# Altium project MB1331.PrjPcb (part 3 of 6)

## Sheet Audio_Codec.SchDoc: Audio Codec
size A4; Date: Not used; ApprovedBy: Not used; CheckedBy: Not used; Author: Not used; CompanyName: STMicroelectronics; DrawnBy: Not used; Engineer: Not used; Organization: Not used; Address1: Not used; Address2: Not used; Address3: Not used; Address4: Not used; DocumentNumber: Not used; Revision: Not used; SheetNumber: 10; SheetTotal: 23
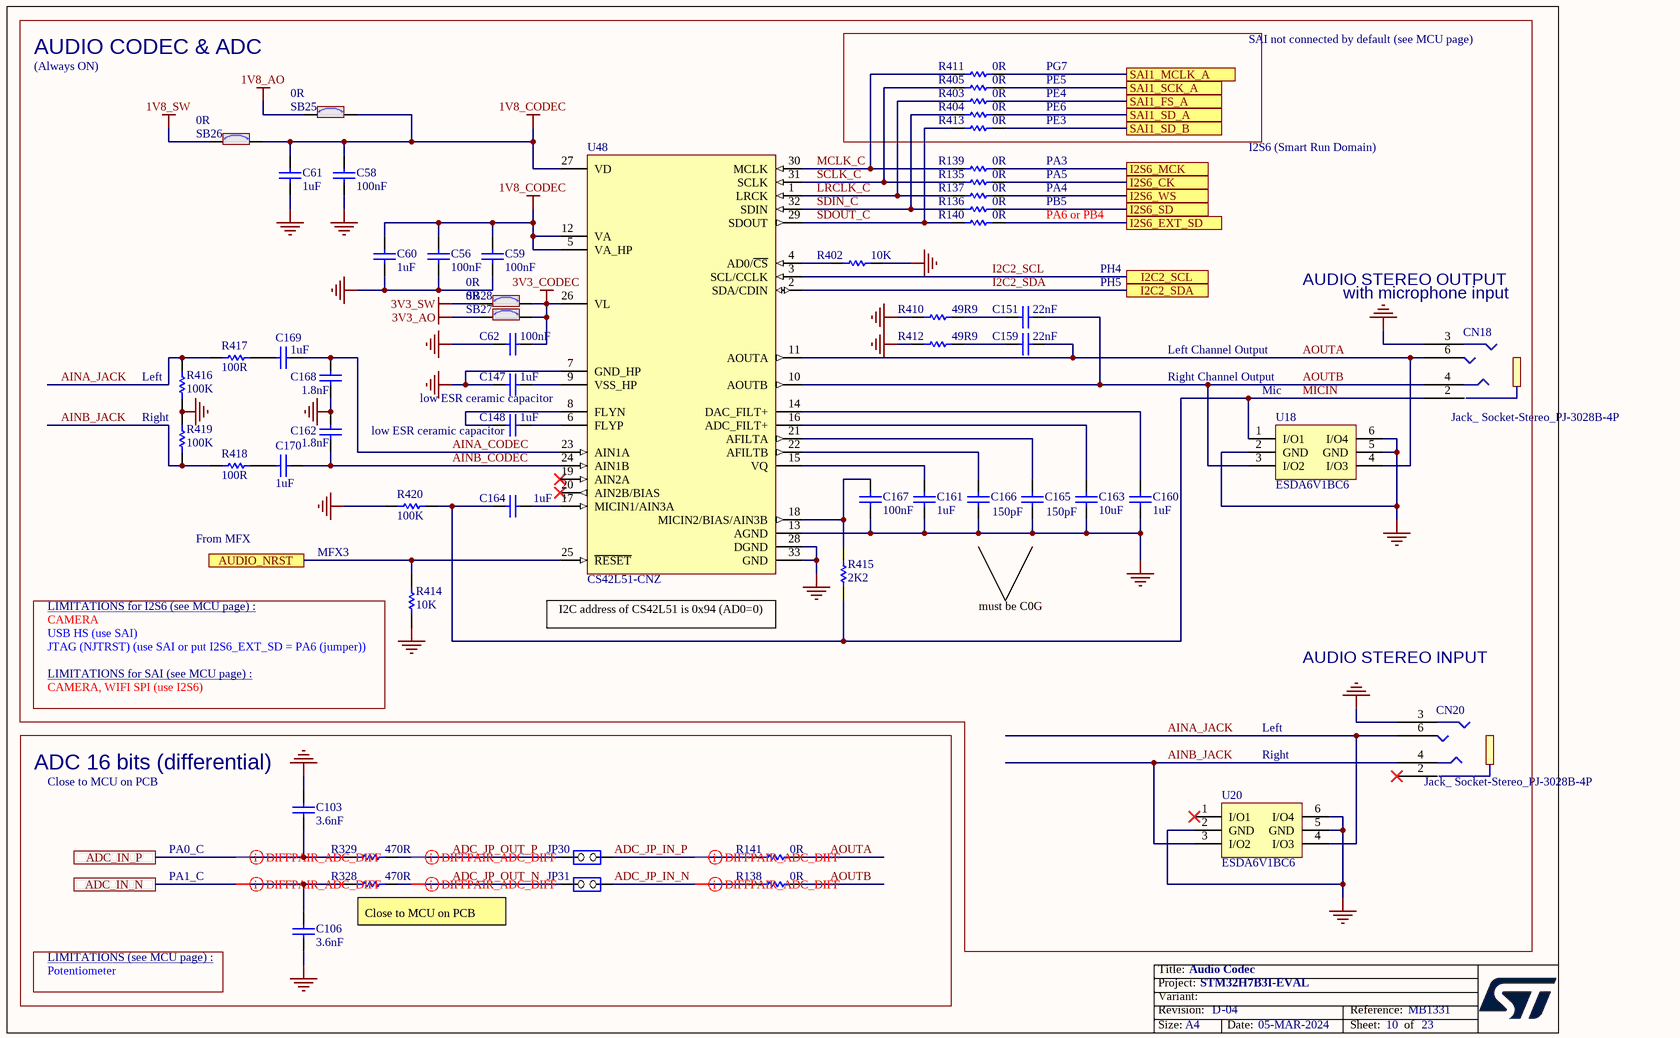
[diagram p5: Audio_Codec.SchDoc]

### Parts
C56  value 100nF  [C0402]  (hidden comment: Capacitor)
C58  value 100nF  [C0402]  (hidden comment: Capacitor)
C59  value 100nF  [C0402]  (hidden comment: Capacitor)
C60  value 1uF  [C0603]  (hidden comment: Capacitor)
C61  value 1uF  [C0603]  (hidden comment: Capacitor)
C62  value 100nF  [C0402]  (hidden comment: Capacitor)
C103  value 3.6nF  [C0603]  (hidden comment: Capacitor)
C106  value 3.6nF  [C0603]  (hidden comment: Capacitor)
C147  value 1uF  [C0603]  (hidden comment: Capacitor)
C148  value 1uF  [C0603]  (hidden comment: Capacitor)
C151  value 22nF  [C0603]  (hidden comment: Capacitor)
C159  value 22nF  [C0603]  (hidden comment: Capacitor)
C160  value 1uF  [C0603]  (hidden comment: Capacitor)
C161  value 1uF  [C0603]  (hidden comment: Capacitor)
C162  value 1.8nF  [C0402]  (hidden comment: Capacitor)
C163  value 10uF  [C0603]  (hidden comment: Capacitor)
C164  value 1uF  [C0603]  (hidden comment: Capacitor)
C165  value 150pF  [C0603]  (hidden comment: Capacitor)
C166  value 150pF  [C0603]  (hidden comment: Capacitor)
C167  value 100nF  [C0402]  (hidden comment: Capacitor)
C168  value 1.8nF  [C0402]  (hidden comment: Capacitor)
C169  value 1uF  [C0402]  (hidden comment: Capacitor)
C170  value 1uF  [C0402]  (hidden comment: Capacitor)
CN18  value Jack_ Socket-Stereo_PJ-3028B-4P  [CON_PHONE-JACK-3P5_HY_PJ3028B]  (hidden comment: Jack_PJ3028B-3_4P)
CN20  value Jack_ Socket-Stereo_PJ-3028B-4P  [CON_PHONE-JACK-3P5_HY_PJ3028B]  (hidden comment: Jack_PJ3028B-3_4P)
JP30  Jumper_Header 2x1  [CON_SAMTEC_TSW-102-07-G-S]  (value not drawn)
JP31  Jumper_Header 2x1  [CON_SAMTEC_TSW-102-07-G-S]  (value not drawn)
R135  value 0R  [R0402]  (hidden comment: Resistor)
R136  value 0R  [R0402]  (hidden comment: Resistor)
R137  value 0R  [R0402]  (hidden comment: Resistor)
R138  value 0R  [R0603]  (hidden comment: Resistor)
R139  value 0R  [R0402]  (hidden comment: Resistor)
R140  value 0R  [R0402]  (hidden comment: Resistor)
R141  value 0R  [R0603]  (hidden comment: Resistor)
R328  value 470R  [R0402]  (hidden comment: Resistor)
R329  value 470R  [R0402]  (hidden comment: Resistor)
R402  value 10K  [R0402]  (hidden comment: Resistor)
R403  value 0R  [R0402]  (hidden comment: Resistor)
R404  value 0R  [R0402]  (hidden comment: Resistor)
R405  value 0R  [R0402]  (hidden comment: Resistor)
R410  value 49R9  [R0603]  (hidden comment: Resistor)
R411  value 0R  [R0402]  (hidden comment: Resistor)
R412  value 49R9  [R0603]  (hidden comment: Resistor)
R413  value 0R  [R0402]  (hidden comment: Resistor)
R414  value 10K  [R0402]  (hidden comment: Resistor)
R415  value 2K2  [R0603]  (hidden comment: Resistor)
R416  value 100K  [R0402]  (hidden comment: Resistor)
R417  value 100R  [R0402]  (hidden comment: Resistor)
R418  value 100R  [R0402]  (hidden comment: Resistor)
R419  value 100K  [R0402]  (hidden comment: Resistor)
R420  value 100K  [R0603]  (hidden comment: Resistor)
SB25  value 0R  [SOLDER-BRIDGE_R0603-0R]  (hidden comment: SB_ON)
SB26  value 0R  [SOLDER-BRIDGE_R0603-0R]  (hidden comment: SB_ON)
SB27  value 0R  [SOLDER-BRIDGE_R0603-0R]  (hidden comment: SB_ON)
SB28  value 0R  [SOLDER-BRIDGE_R0603-0R]  (hidden comment: SB_ON)
U18  ESDA6V1BC6  [ESD_SOT23-6L]
U20  ESDA6V1BC6  [ESD_SOT23-6L]
U48  CS42L51-CNZ  [ICC_QFN32-EPAD_5X5_P050]

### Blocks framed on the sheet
AUDIO CODEC & ADC: C56 C58-C62 C147 C148 C151 C159-C170 CN18 CN20 R135-R137 R139 R140 R402-R405 R410-R420 SB25-SB28 U18 U20 U48
ADC 16 bits (differential): C103 C106 JP30 JP31 R138 R141 R328 R329

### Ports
ADC_IN_N, ADC_IN_P, AUDIO_NRST, I2C2_SCL, I2C2_SDA, I2S6_CK, I2S6_EXT_SD, I2S6_MCK, I2S6_SD, I2S6_WS, SAI1_FS_A, SAI1_MCLK_A, SAI1_SCK_A, SAI1_SD_A, SAI1_SD_B

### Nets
1V8_AO: SB25.1
1V8_CODEC: C56.2 C58.2 C59.2 C60.1 C61.1 SB25.2 SB26.2 U48.5(VA_HP) U48.12(VA) U48.27(VD)
1V8_SW: SB26.1
3V3_AO: SB27.1
3V3_CODEC: C62.1 SB27.2 SB28.2 U48.26(VL)
3V3_SW: SB28.1
GND: C56.1 C58.1 C59.1 C60.2 C61.2 C62.2 C103.2 C106.1 C147.1 C160.1 C161.1 C162.2 C163.1 C165.2 C166.2 C167.2 C168.1 CN18.3 CN20.3 R402.2 R410.1 R412.1 R414.1 R416.1 R419.2 R420.1 U18.2(GND) U18.5(GND) U18.6(I/O4) U20.2(GND) U20.5(GND) U20.6(I/O4) U48.7(GND_HP) U48.13(AGND) U48.28(DGND) U48.33(GND)
ADC_IN_N: C106.2 R328.1 ; port ADC_IN_N
ADC_IN_P: C103.1 R329.1 ; port ADC_IN_P
ADC_JP_IN_N: JP31.1(COMMON) R138.1
ADC_JP_IN_P: JP30.1(COMMON) R141.1
ADC_JP_OUT_N: JP31.2(NO) R328.2
ADC_JP_OUT_P: JP30.2(NO) R329.2
AINA_CODEC: C168.2 C169.2 U48.23(AIN1A)
AINA_JACK: CN20.6 R416.2 R417.1 U20.4(I/O3)
AINB_CODEC: C162.1 C170.2 U48.24(AIN1B)
AINB_JACK: CN20.4 R418.1 R419.1 U20.3(I/O2)
AOUTA: C159.2 CN18.6 R141.2 U18.4(I/O3) U48.11(AOUTA)
AOUTB: C151.2 CN18.4 R138.2 U18.3(I/O2) U48.10(AOUTB)
AUDIO_NRST: R414.2 U48.25(~{RESET}) ; port AUDIO_NRST
I2C2_SCL: U48.3(SCL/CCLK) ; port I2C2_SCL
I2C2_SDA: U48.2(SDA/CDIN) ; port I2C2_SDA
I2S6_CK: R135.2 ; port I2S6_CK
I2S6_EXT_SD: R140.2 ; port I2S6_EXT_SD
I2S6_MCK: R139.2 ; port I2S6_MCK
I2S6_SD: R136.2 ; port I2S6_SD
I2S6_WS: R137.2 ; port I2S6_WS
LRCLK_C: R137.1 R403.1 U48.1(LRCK)
MCLK_C: R139.1 R411.1 U48.30(MCLK)
MICIN: C164.1 CN18.2 R415.1 R420.2 U18.1(I/O1)
SAI1_FS_A: R403.2 ; port SAI1_FS_A
SAI1_MCLK_A: R411.2 ; port SAI1_MCLK_A
SAI1_SCK_A: R405.2 ; port SAI1_SCK_A
SAI1_SD_A: R404.2 ; port SAI1_SD_A
SAI1_SD_B: R413.2 ; port SAI1_SD_B
SCLK_C: R135.1 R405.1 U48.31(SCLK)
SDIN_C: R136.1 R404.1 U48.32(SDIN)
SDOUT_C: R140.1 R413.1 U48.29(SDOUT)
NetC147_2: C147.2 U48.9(VSS_HP)
NetC148_1: C148.1 U48.8(FLYN)
NetC148_2: C148.2 U48.6(FLYP)
NetC151_1: C151.1 R410.2
NetC159_1: C159.1 R412.2
NetC160_2: C160.2 U48.14(DAC_FILT+)
NetC161_2: C161.2 U48.15(VQ)
NetC163_2: C163.2 U48.16(ADC_FILT+)
NetC164_2: C164.2 U48.17(MICIN1/AIN3A)
NetC165_1: C165.1 U48.21(AFILTA)
NetC166_1: C166.1 U48.22(AFILTB)
NetC167_1: C167.1 R415.2 U48.18(MICIN2/BIAS/AIN3B)
NetC169_1: C169.1 R417.2
NetC170_1: C170.1 R418.2
NetR402_1: R402.1 U48.4(AD0/~{CS})

Not connected (* = marked no-connect by the designer): CN20 2*; U20 1(I/O1)*; U48 19(AIN2A)* 20(AIN2B/BIAS)*

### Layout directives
differential pair: ADC_IN_N, ADC_IN_P, ADC_JP_IN_N, ADC_JP_IN_P, ADC_JP_OUT_N, ADC_JP_OUT_P

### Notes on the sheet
- SAI not connected by default (see MCU page)
- (Always ON)
- PE6
- PE4
- PE5
- PG7
- PA5
- PA3
- PE3
- I2S6 (Smart Run Domain)
- PA4
- PA6 or PB4
- PB5
- PH4
- PH5
- AUDIO STEREO OUTPUT
- (near CN18) with microphone input
- (near R416) Left
- Left Channel Output
- Right Channel Output
- Right
- (near C148) low ESR ceramic capacitor
- low ESR ceramic capacitor
- (near U18) Mic
- From MFX
- MFX3
- LIMITATIONS for I2S6 (see MCU page) :
- CAMERA
- USB HS (use SAI)
- (near R414) JTAG (NJTRST) (use SAI or put I2S6_EXT_SD = PA6 (jumper))
- (near U48) I2C address of CS42L51 is 0x94 (AD0=0)
- must be C0G
- LIMITATIONS for SAI (see MCU page) :
- CAMERA, WIFI SPI (use I2S6)
- AUDIO STEREO INPUT
- Close to MCU on PCB
- Left
- PA0_C
- PA1_C
- (near R328) Close to MCU on PCB
- LIMITATIONS (see MCU page) :
- Potentiometer

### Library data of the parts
C56 C58 C59 C62 C167 = MCD-00006: Capacitor, MLCC, 100nF, 16V, X7R, 10%, 0402, T=0.5mm; Manufacturer_Part_Number: CC0402KRX7R7BB104; Manufacturer: YAGEO; Alternate_Manufacturer_Part_Number: GCM155R71C104KA55D; Alternate_Manufacturer: MURATA; Part_Preference: Recommended; Partial_Alternate_Internal_Part_Number: MCD-03299; Provided_By: SUBCO; ECCN_US: EAR99; ECCN_EU: NEC; Component_Country_Of_Origin: China; ID: 2474; Order_Code_RS: 9402047; ShowFields: YES
C60 C61 C147 C148 C160 C161 C164 = MCD-00010: Capacitor, MLCC, 1uF, 16V, X5R, 10%, 0603, T=0,8mm; Manufacturer_Part_Number: CC0603KRX5R7BB105; Manufacturer: YAGEO; Part_Preference: Recommended; Provided_By: SUBCO; ECCN_US: EAR99; ECCN_EU: NEC; Component_Country_Of_Origin: China; ID: 2470; Order_Code_RS: 2370680; ShowFields: YES
C103 C106 = MCD-00716: Capacitor, MLCC, 3.6nF, 50V, C0G, 5%, 0603, T=0,8mm; Manufacturer_Part_Number: C0603C362J5GACTU; Manufacturer: KEMET; Alternate_Manufacturer_Part_Number: GRM1885C1H362JA01D; Alternate_Manufacturer: MURATA; Part_Preference: Recommended; Provided_By: SUBCO; ECCN_US: EAR99; ECCN_EU: NEC; Component_Country_Of_Origin: Mexico; ID: 3031; ShowFields: YES
C151 C159 = MCD-00555: Capacitor, MLCC, 22nF, 10%, 25V, X7R, 0603, T=0,8mm; Manufacturer_Part_Number: CC0603KRX7R8BB223; Manufacturer: YAGEO; Part_Preference: Recommended; Provided_By: SUBCO; ECCN_US: EAR99; ECCN_EU: NEC; Component_Country_Of_Origin: China; ID: 3190; ShowFields: YES
C162 C168 = MCD-00694: Capacitor, MLCC, 1.8nF, 50V, X7R, 10%, 0402, T=0.5mm; Manufacturer_Part_Number: CC0402KRX7R9BB182; Manufacturer: YAGEO; Part_Preference: Recommended; Provided_By: SUBCO; Component_Country_Of_Origin: China; ID: 3045; ShowFields: YES
C163 = MCD-00099: Capacitor, MLCC, 10uF, 10V, X5R, 10%, 0603, T=0,8mm; Manufacturer_Part_Number: GRM188R61A106KE69D; Manufacturer: MURATA; Part_Preference: Recommended; Partial_Alternate_Internal_Part_Number: MCD-03152; Provided_By: SUBCO; ECCN_US: EAR99; ECCN_EU: NEC; Component_Country_Of_Origin: Japan°°; ID: 2770; Order_Code_RS: 2494233; ShowFields: YES
C165 C166 = MCD-00304: Capacitor, MLCC, 150pF, 50V, COG, 5%, 0603, T=0,8mm; Manufacturer_Part_Number: CC0603JRNPO9BN151; Manufacturer: YAGEO; BMS_Part_Number: 9142051; Part_Preference: Recommended; Provided_By: SUBCO; ECCN_US: EAR99; ECCN_EU: NEC; Component_Country_Of_Origin: China; ID: 2568; ShowFields: YES
C169 C170 = MCD-00095: Capacitor, MLCC, 1uF, 6V3, X5R, 10%, 0402, T=0,5mm; Manufacturer_Part_Number: GRM155R61E105KA12; Manufacturer: MURATA; Alternate_Manufacturer_Part_Number: GRM155R60J105KE19; Part_Preference: Recommended; Provided_By: SUBCO; ECCN_US: EAR99; ECCN_EU: NEC; Component_Country_Of_Origin: Japan°°; ID: 2772; Order_Code_RS: 2218855; ShowFields: YES
CN18 CN20 = MCD-00263: Connector Jack Socket Stereo 3.5mm, 4 pins, RA, SMT, Black; Manufacturer_Part_Number: PJ-3028B-4P; Manufacturer: QIAOD; Part_Preference: Recommended; Provided_By: SUBCO; Component_Country_Of_Origin: Unknown; ID: 2608; ShowFields: YES
JP30 JP31 = MCD-00045: Header, 2x1, 2,54mm, VR, TH, Height 5.84mm/2.54mm; Part_Type: Connector; Manufacturer_Part_Number: TSW-102-07-G-S; Manufacturer: SAMTEC; Alternate_Manufacturer_Part_Number: 313102S111116;313102S111116; Alternate_Manufacturer: JIUBABA; LIANYI; Full_Alternate_Internal_Part_Number: MCD-02390; Part_Preference: Recommended; Partial_Alternate_Internal_Part_Number: MCD-02957, MCD-03720; Provided_By: SUBCO; Component_Country_Of_Origin: China, Costa Rica, Malaysia, USA, Vietnam; ID: 2545; Order_Code_RS: 2505044; ShowFields: YES
R135-R137 R139 R140 R403-R405 R411 R413 = MCD-00052: Resistor,0R,0402,5%,1/16W; Manufacturer_Part_Number: RC0402JR-070RL; Manufacturer: YAGEO; Part_Preference: Recommended; Provided_By: SUBCO; ECCN_US: EAR99; ECCN_EU: NEC; Component_Country_Of_Origin: China; ID: 2540; Order_Code_RS: 9232516RL; ShowFields: YES
R138 R141 = MCD-00056: Resistor,0R,0603,5%,1/10W; Manufacturer_Part_Number: RC0603JR-070RL; Manufacturer: YAGEO; Part_Preference: Recommended; Provided_By: SUBCO; ECCN_US: EAR99; ECCN_EU: NEC; Component_Country_Of_Origin: China; ID: 2536; Order_Code_RS: 9233130RL; ShowFields: YES
R328 R329 = MCD-00178: Resistor,470R,0402,1%,1/16W; Manufacturer_Part_Number: RC0402FR-07470RL; Manufacturer: YAGEO; Part_Preference: Recommended; Provided_By: SUBCO; ECCN_US: EAR99; ECCN_EU: NEC; Component_Country_Of_Origin: China; ID: 2689; ShowFields: YES
R402 R414 = MCD-00053: Resistor,10K,0402,1%,1/16W; Manufacturer_Part_Number: RC0402FR-0710KL; Manufacturer: YAGEO; BMS_Part_Number: 9131590; Part_Preference: Recommended; Provided_By: SUBCO; ECCN_US: EAR99; ECCN_EU: NEC; Component_Country_Of_Origin: China; ID: 2539; Order_Code_RS: 9239359; ShowFields: YES
R410 R412 = MCD-00564: Resistor,49R9,0603,1%,1/10W; Manufacturer_Part_Number: RC0603FR-0749R9L; Manufacturer: YAGEO; Part_Preference: Recommended; Provided_By: SUBCO; ECCN_US: EAR99; ECCN_EU: NEC; Component_Country_Of_Origin: China; ID: 3180; ShowFields: YES
R415 = MCD-00349: Resistor,2K2,0603,1%,1/10W; Manufacturer_Part_Number: RC0603FR-072K2L; Manufacturer: YAGEO; Part_Preference: Recommended; Provided_By: SUBCO; ECCN_US: EAR99; ECCN_EU: NEC; Component_Country_Of_Origin: China; ID: 2929; ShowFields: YES
R416 R419 = MCD-00059: Resistor,100K,0402,1%,1/16W; Manufacturer_Part_Number: RC0402FR-07100KL; Manufacturer: YAGEO; Alternate_Manufacturer_Part_Number: RT0402FRE07100KL; Part_Preference: Recommended; Partial_Alternate_Internal_Part_Number: MCD-03301; Provided_By: SUBCO; ECCN_US: EAR99; ECCN_EU: NEC; Component_Country_Of_Origin: China; ID: 2533; Order_Code_RS: 2421891; ShowFields: YES
R417 R418 = MCD-00067: Resistor,100R,0402,1%,1/16W; Manufacturer_Part_Number: RC0402FR-07100RL; Manufacturer: YAGEO; Part_Preference: Recommended; Provided_By: SUBCO; ECCN_US: EAR99; ECCN_EU: NEC; Component_Country_Of_Origin: China; ID: 2527; Order_Code_RS: 9239111; ShowFields: YES
R420 = MCD-00223: Resistor,100K,0603,1%,1/10W; Manufacturer_Part_Number: RC0603FR-07100KL; Manufacturer: YAGEO; Part_Preference: Recommended; Provided_By: SUBCO; ECCN_US: EAR99; ECCN_EU: NEC; Component_Country_Of_Origin: China; ID: 2647; ShowFields: YES
SB25-SB28 = MCD-00071: Solder Bridge ON; Part_Type: Resistor; Manufacturer_Part_Number: RC0603JR-070RL; Manufacturer: YAGEO; Manufacturer_HQ_COO: Unknown; Part_Preference: Recommended; Provided_By: SUBCO; Component_Country_Of_Origin: China; ID: 2521; Order_Code_RS: 199-5647; ShowFields: YES
U18 U20 = MCD-00247: Quad Bidir ESD protection; Manufacturer: STMICROELECTRONICS; Part_Type: Diode; BMS_Part_Number: 9179038; Manufacturer_HQ_COO: EU; Part_Preference: Recommended; Provided_By: SUBCO with ST control; ECCN_US: EAR99; ECCN_EU: NEC; Component_Country_Of_Origin: China; ID: 2624; Order_Code_RS: 248-805; ShowFields: YES
U48 = MCD-00265: Low-Power, Stereo Codec with Headphone Amp; Manufacturer: CIRRUS LOGIC; Part_Type: IC; Part_Preference: Forbidden; Provided_By: SUBCO; ECCN_US: EAR99; ECCN_EU: NEC; Component_Country_Of_Origin: China°; ID: 2602; ShowFields: YES

## Sheet DFSDM_Audio&Motor.SchDoc: Audio & Motor DFSDM
size A4; Date: Not used; ApprovedBy: Not used; CheckedBy: Not used; Author: Not used; CompanyName: STMicroelectronics; DrawnBy: Not used; Engineer: Not used; Organization: Not used; Address1: Not used; Address2: Not used; Address3: Not used; Address4: Not used; DocumentNumber: Not used; Revision: Not used; SheetNumber: 11; SheetTotal: 23
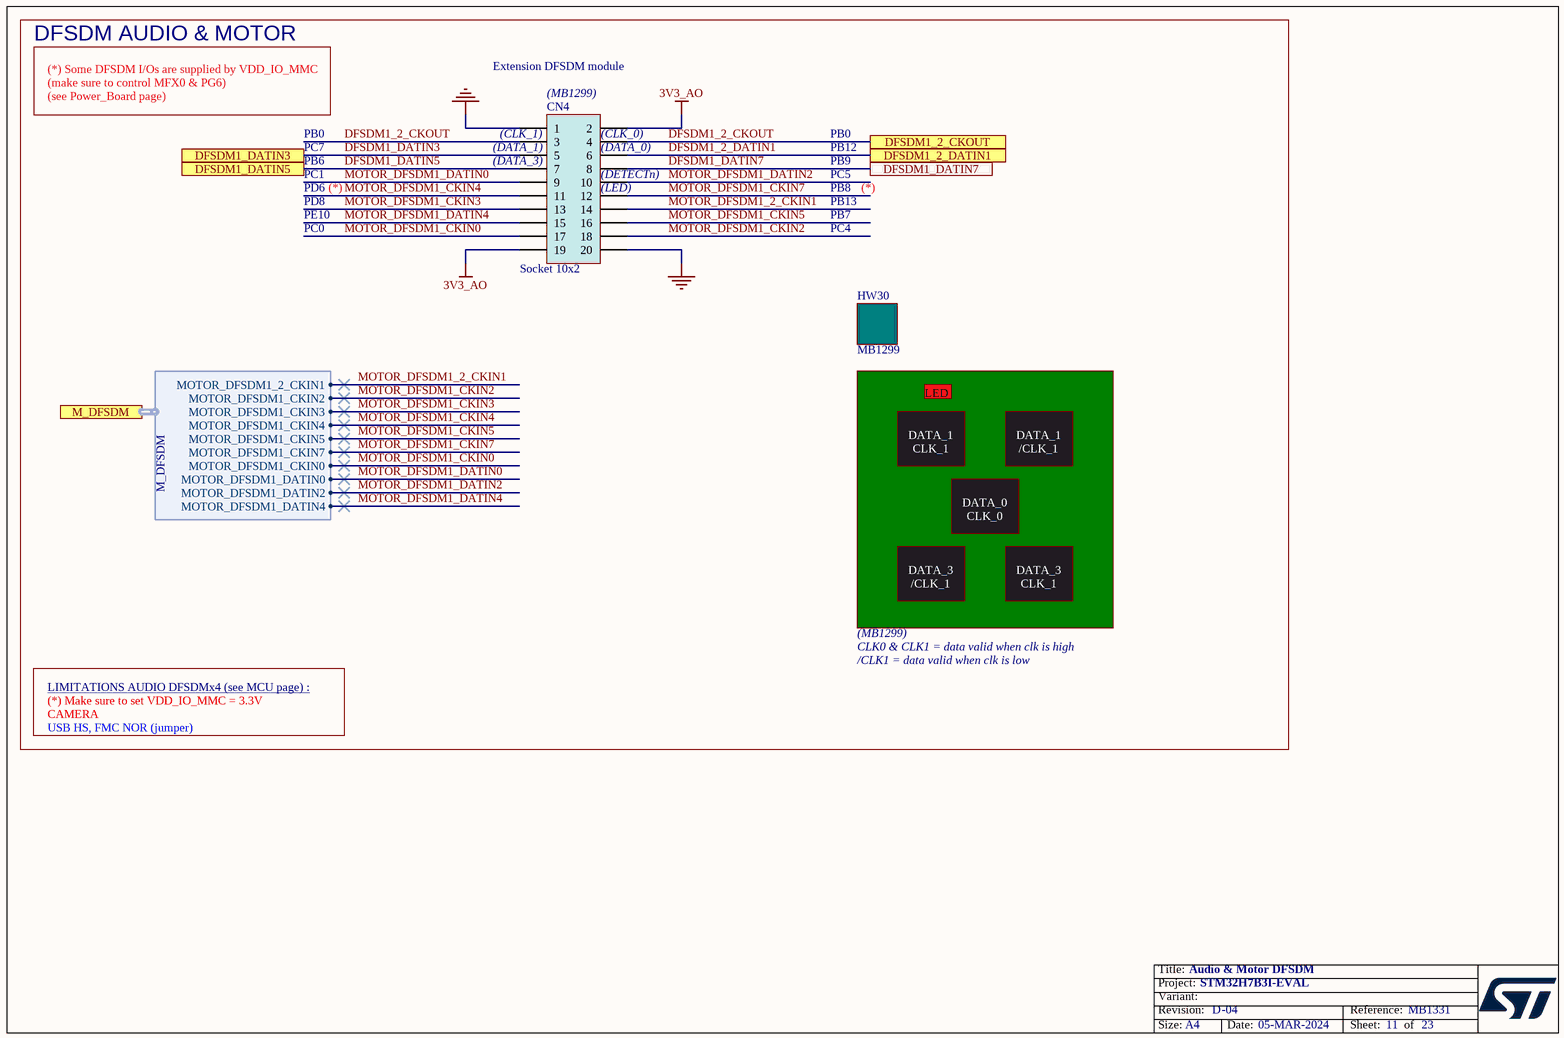
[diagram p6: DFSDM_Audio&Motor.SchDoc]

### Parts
CN4  Socket 10x2  [CON_FCI_20021311-XXX20XXLF]
HW30  value MB1299  [MOD_MB1299_5-MEMS_MICROPHONE-EXPANSION-BOARD]  (hidden comment: Daughter_Board)

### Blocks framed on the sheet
DFSDM AUDIO & MOTOR: CN4 HW30

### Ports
DFSDM1_2_CKOUT, DFSDM1_2_DATIN1, DFSDM1_DATIN3, DFSDM1_DATIN5, DFSDM1_DATIN7, M_DFSDM (harness M_DFSDM)

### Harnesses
M_DFSDM: MOTOR_DFSDM1_2_CKIN1, MOTOR_DFSDM1_CKIN3, MOTOR_DFSDM1_CKIN5, MOTOR_DFSDM1_CKIN7, MOTOR_DFSDM1_CKIN2, MOTOR_DFSDM1_CKIN4, MOTOR_DFSDM1_CKIN0, MOTOR_DFSDM1_DATIN0, MOTOR_DFSDM1_DATIN2, MOTOR_DFSDM1_DATIN4

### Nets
3V3_AO: CN4.2 CN4.19
GND: CN4.1 CN4.20
DFSDM1_2_CKOUT: CN4.3 CN4.4 ; port DFSDM1_2_CKOUT
DFSDM1_2_DATIN1: CN4.6 ; port DFSDM1_2_DATIN1
DFSDM1_DATIN3: CN4.5 ; port DFSDM1_DATIN3
DFSDM1_DATIN5: CN4.7 ; port DFSDM1_DATIN5
DFSDM1_DATIN7: CN4.8 ; port DFSDM1_DATIN7
MOTOR_DFSDM1_2_CKIN1: CN4.14 ; port M_DFSDM.MOTOR_DFSDM1_2_CKIN1
MOTOR_DFSDM1_CKIN0: CN4.17 ; port M_DFSDM.MOTOR_DFSDM1_CKIN0
MOTOR_DFSDM1_CKIN2: CN4.18 ; port M_DFSDM.MOTOR_DFSDM1_CKIN2
MOTOR_DFSDM1_CKIN3: CN4.13 ; port M_DFSDM.MOTOR_DFSDM1_CKIN3
MOTOR_DFSDM1_CKIN4: CN4.11 ; port M_DFSDM.MOTOR_DFSDM1_CKIN4
MOTOR_DFSDM1_CKIN5: CN4.16 ; port M_DFSDM.MOTOR_DFSDM1_CKIN5
MOTOR_DFSDM1_CKIN7: CN4.12 ; port M_DFSDM.MOTOR_DFSDM1_CKIN7
MOTOR_DFSDM1_DATIN0: CN4.9 ; port M_DFSDM.MOTOR_DFSDM1_DATIN0
MOTOR_DFSDM1_DATIN2: CN4.10 ; port M_DFSDM.MOTOR_DFSDM1_DATIN2
MOTOR_DFSDM1_DATIN4: CN4.15 ; port M_DFSDM.MOTOR_DFSDM1_DATIN4

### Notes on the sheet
- (*) Some DFSDM I/Os are supplied by VDD_IO_MMC
  (make sure to control MFX0 & PG6)
  (see Power_Board page)
- Extension DFSDM module
- (near CN4) (MB1299)
- PB0
- PB6
- PC7
- PC1
- (near CN4) (DATA_1)
- (near CN4) (DATA_3)
- (near CN4) (CLK_1)
- (near CN4) (CLK_0)
- (near CN4) (DATA_0)
- (near CN4) (DETECTn)
- PB12
- PB9
- PC5
- PD8
- PC0
- PD6
- PE10
- (*)
- (near CN4) (LED)
- PB13
- PB8
- PB7
- PC4
- DATA_1
  CLK_1
- LED
- DATA_1
  /CLK_1
- DATA_0
  CLK_0
- DATA_3
  /CLK_1
- DATA_3
  CLK_1
- (MB1299)
- CLK0 & CLK1 = data valid when clk is high
- LIMITATIONS AUDIO DFSDMx4 (see MCU page) :
- CAMERA
- (*) Make sure to set VDD_IO_MMC = 3.3V
- /CLK1 = data valid when clk is low
- USB HS, FMC NOR (jumper)

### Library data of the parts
CN4 = MCD-00147: Socket for MB1299, 10x2, 1.27mm, VR, TH, Height 4.30mm/2.40mm; Manufacturer_Part_Number: 20021311-00020T4LF; Manufacturer: AMPHENOL ICC; Part_Type: Connector; Alternate_Manufacturer_Part_Number: 234220S1410; Alternate_Manufacturer: JIUBABA; Part_Preference: Recommended; Partial_Alternate_Internal_Part_Number: MCD-03007; Provided_By: SUBCO; ECCN_US: EAR99; ECCN_EU: NEC; Component_Country_Of_Origin: China; ID: 2719; Order_Code_RS: 170-8859; ShowFields: YES
HW30 = MCD-01031: MB1299 : Expansion Board with 5 x MEMS Microphones; Part_Type: Misc; Manufacturer_Part_Number: MB1299 - 5 x MEMS Microphones Expansion Board; Manufacturer: STMICROELECTRONICS; Manufacturer_HQ_COO: EU; Part_Preference: Recommended; Provided_By: SUBCO with ST control; Component_Country_Of_Origin: Unknown; ID: 2993; ShowFields: YES

## Sheet LCD.SchDoc: LCD
size A4; Date: Not used; ApprovedBy: Not used; CheckedBy: Not used; Author: Not used; CompanyName: STMicroelectronics; DrawnBy: Not used; Engineer: Not used; Organization: Not used; Address1: Not used; Address2: Not used; Address3: Not used; Address4: Not used; DocumentNumber: Not used; Revision: Not used; SheetNumber: 13; SheetTotal: 23
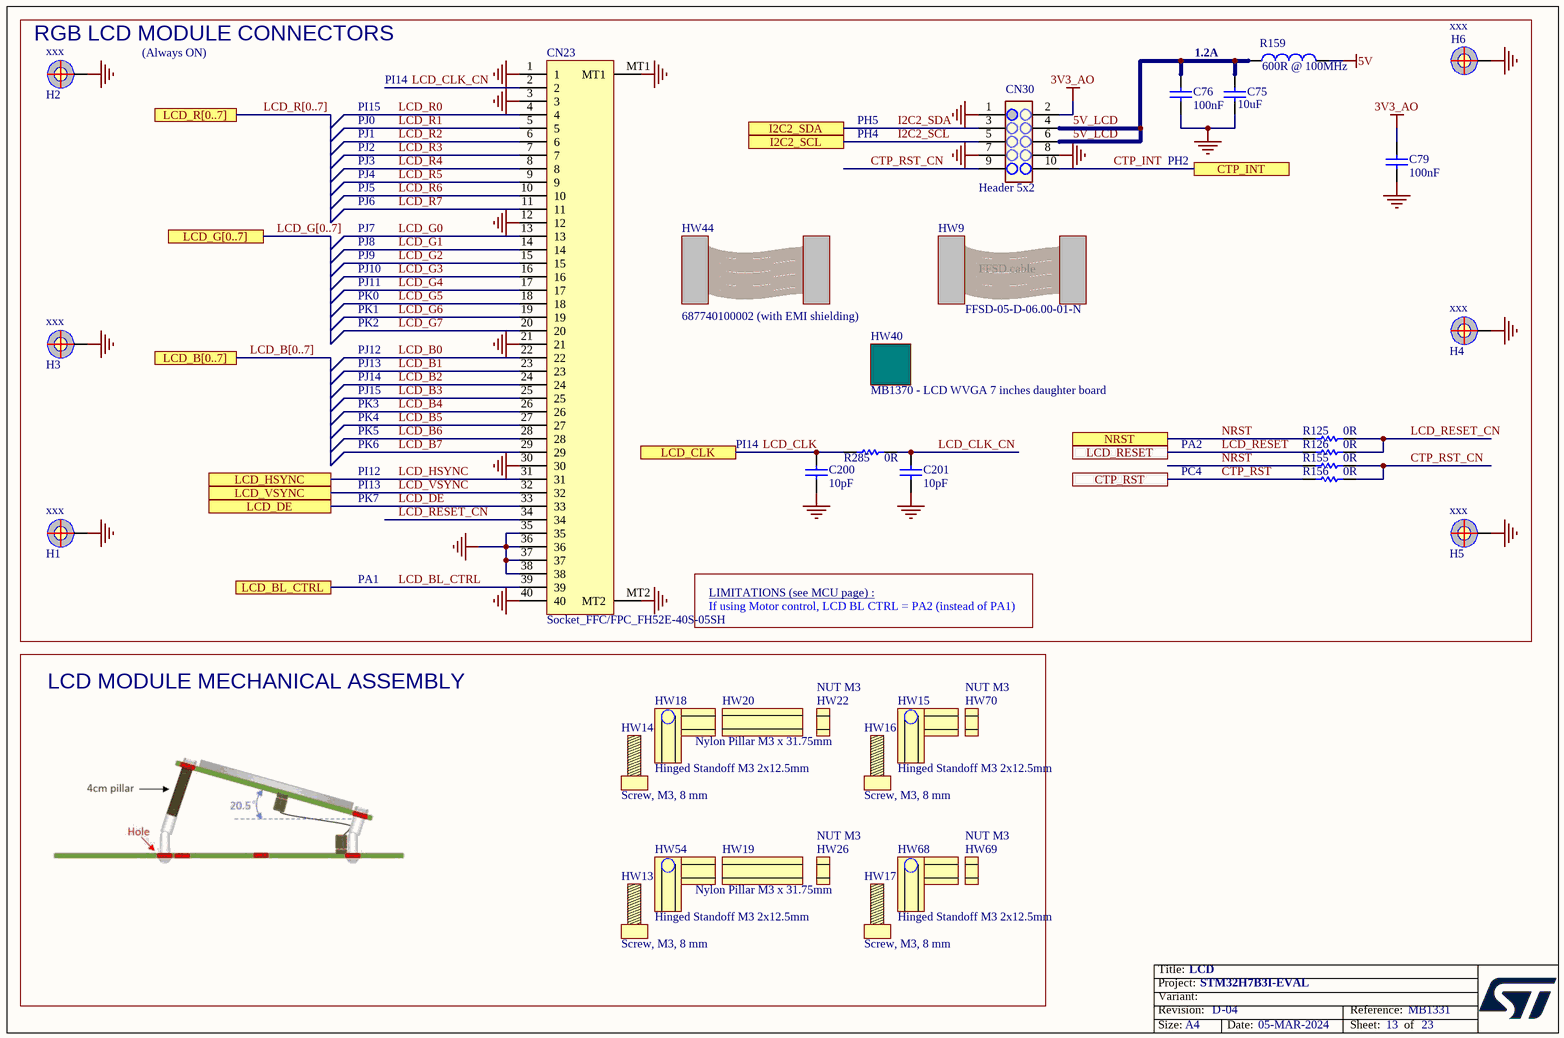
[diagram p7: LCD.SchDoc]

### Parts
C75  value 10uF  [C0805]  (hidden comment: Capacitor)
C76  value 100nF  [C0402]  (hidden comment: Capacitor)
C79  value 100nF  [C0402]  (hidden comment: Capacitor)
C200  value 10pF  [C0402]  (hidden comment: Capacitor)
C201  value 10pF  [C0402]  (hidden comment: Capacitor)
CN23  value Socket_FFC/FPC_FH52E-40S-05SH  [CON_HRS_FH52E-40S-05SH]  (hidden comment: FH52E-40S-0.5SH)
CN30  value Header 5x2  [CON_SAMTEC_FTSH-105-01-L-DV-K]  (hidden comment: Header 5x2 Generic)
H1  value xxx  [PTH_M1261-3005-N_3P5X6_M3_H14]  (hidden comment: POSITION HOLE)  (no BOM)
H2  value xxx  [PTH_M1261-3005-N_3P5X6_M3_H14]  (hidden comment: POSITION HOLE)  (no BOM)
H3  value xxx  [PTH_M1261-3005-N_3P5X6_M3_H14]  (hidden comment: POSITION HOLE)  (no BOM)
H4  value xxx  [PTH_M1261-3005-N_3P5X6_M3_H14]  (hidden comment: POSITION HOLE)  (no BOM)
H5  value xxx  [PTH_M1261-3005-N_3P5X6_M3_H14]  (hidden comment: POSITION HOLE)  (no BOM)
H6  value xxx  [PTH_M1261-3005-N_3P5X6_M3_H14]  (hidden comment: POSITION HOLE)  (no BOM)
HW9  value FFSD-05-D-06.00-01-N  (hidden comment: FFSD05_CABLE)  (mechanical)
HW13  value Screw, M3, 8 mm  (hidden comment: SCREW)  (no BOM)
HW14  value Screw, M3, 8 mm  (hidden comment: SCREW)  (no BOM)
HW15  value Hinged Standoff M3 2x12.5mm  (hidden comment: Hinged_Standoff)  (no BOM)
HW16  value Screw, M3, 8 mm  (hidden comment: SCREW)  (no BOM)
HW17  value Screw, M3, 8 mm  (hidden comment: SCREW)  (no BOM)
HW18  value Hinged Standoff M3 2x12.5mm  (hidden comment: Hinged_Standoff)  (no BOM)
HW19  value Nylon Pillar M3 x 31.75mm  (hidden comment: PILLAR)  (no BOM)
HW20  value Nylon Pillar M3 x 31.75mm  (hidden comment: PILLAR)  (no BOM)
HW22  value NUT M3  (hidden comment: NUT)  (no BOM)
HW26  value NUT M3  (hidden comment: NUT)  (no BOM)
HW40  value MB1370 - LCD WVGA 7 inches daughter board  [LCD_DRAWING_ROCKTEK_RK070ER9427L]  (hidden comment: Daughter_Board)
HW44  value 687740100002 (with EMI shielding)  (hidden comment: CABLE)  (mechanical)
HW54  value Hinged Standoff M3 2x12.5mm  (hidden comment: Hinged_Standoff)  (no BOM)
HW68  value Hinged Standoff M3 2x12.5mm  (hidden comment: Hinged_Standoff)  (no BOM)
HW69  value NUT M3  (hidden comment: NUT)  (no BOM)
HW70  value NUT M3  (hidden comment: NUT)  (no BOM)
R125  value 0R  [R0603]  (hidden comment: Resistor)
R126  value 0R  [R0603]  (hidden comment: Resistor)
R155  value 0R  [R0603]  (hidden comment: Resistor)
R156  value 0R  [R0603]  (hidden comment: Resistor)
R159  value 600R @ 100MHz  [IND_0603_H0P8]  (hidden comment: Inductor)
R285  value 0R  [R0603]  (hidden comment: Resistor)

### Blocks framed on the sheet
RGB LCD MODULE CONNECTORS: C75 C76 C79 C200 C201 CN23 CN30 H1-H6 HW9 HW40 HW44 R125 R126 R155 R156 R159 R285
LCD MODULE MECHANICAL ASSEMBLY: HW13-HW20 HW22 HW26 HW54 HW68-HW70

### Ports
CTP_INT, CTP_RST, I2C2_SCL, I2C2_SDA, LCD_B[0..7], LCD_BL_CTRL, LCD_CLK, LCD_DE, LCD_G[0..7], LCD_HSYNC, LCD_R[0..7], LCD_RESET, LCD_VSYNC, NRST

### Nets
3V3_AO: C79.2 CN30.2
5V: R159.2
GND: C75.1 C76.2 C79.1 C200.1 C201.1 CN23.1 CN23.3 CN23.12 CN23.21 CN23.30 CN23.35 CN23.36 CN23.37 CN23.38 CN23.40 CN23.MT1 CN23.MT2 CN30.1 CN30.7 CN30.8 H1.1 H2.1 H3.1 H4.1 H5.1 H6.1
5V_LCD: C75.2 C76.1 CN30.4 CN30.6 R159.1
CTP_INT: CN30.10 ; port CTP_INT
CTP_RST: R156.1 ; port CTP_RST
CTP_RST_CN: CN30.9 R155.2 R156.2
I2C2_SCL: CN30.5 ; port I2C2_SCL
I2C2_SDA: CN30.3 ; port I2C2_SDA
LCD_B0: CN23.22
LCD_B1: CN23.23
LCD_B2: CN23.24
LCD_B3: CN23.25
LCD_B4: CN23.26
LCD_B5: CN23.27
LCD_B6: CN23.28
LCD_B7: CN23.29
LCD_BL_CTRL: CN23.39 ; port LCD_BL_CTRL
LCD_CLK: C200.2 R285.1 ; port LCD_CLK
LCD_CLK_CN: C201.2 CN23.2 R285.2
LCD_DE: CN23.33 ; port LCD_DE
LCD_G0: CN23.13
LCD_G1: CN23.14
LCD_G2: CN23.15
LCD_G3: CN23.16
LCD_G4: CN23.17
LCD_G5: CN23.18
LCD_G6: CN23.19
LCD_G7: CN23.20
LCD_HSYNC: CN23.31 ; port LCD_HSYNC
LCD_R0: CN23.4
LCD_R1: CN23.5
LCD_R2: CN23.6
LCD_R3: CN23.7
LCD_R4: CN23.8
LCD_R5: CN23.9
LCD_R6: CN23.10
LCD_R7: CN23.11
LCD_RESET: R126.1 ; port LCD_RESET
LCD_RESET_CN: CN23.34 R125.2 R126.2
LCD_VSYNC: CN23.32 ; port LCD_VSYNC
NRST: R125.1 R155.1 ; port NRST

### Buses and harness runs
bus LCD_B[0..7] = port LCD_B[0..7]
bus LCD_G[0..7] = port LCD_G[0..7]
bus LCD_R[0..7] = port LCD_R[0..7]

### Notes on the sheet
- (Always ON)
- PI15
- PI14
- 1.2A
- PJ0
- PJ1
- PJ2
- PJ3
- PJ4
- PH5
- PH4
- PH2
- PJ5
- PJ6
- PJ7
- PJ8
- PJ9
- PJ10
- PJ11
- PK0
- PK1
- PK2
- PJ12
- PJ13
- PJ14
- PJ15
- PK3
- PK4
- PK5
- PK6
- PA2
- PI12
- PI13
- PK7
- PC4
- PA1
- LIMITATIONS (see MCU page) :
- If using Motor control, LCD BL CTRL = PA2 (instead of PA1)

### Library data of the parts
C75 = MCD-00014: Capacitor, MLCC, 10uF, 25V, X5R, 10%, 0805, T=0,85mm; Manufacturer_Part_Number: CC0805KRX5R8BB106; Manufacturer: YAGEO; Full_Alternate_Internal_Part_Number: MCD-02385; Part_Preference: Recommended; Partial_Alternate_Internal_Part_Number: MCD-03053; Provided_By: SUBCO; ECCN_US: EAR99; ECCN_EU: NEC; Component_Country_Of_Origin: China; ID: 2468; ShowFields: YES
C76 C79 = MCD-00006: as C56 on sheet Audio_Codec
C200 C201 = MCD-00015: Capacitor, MLCC, 10pF, 50V, NPO, 5%, 0402, T=0,5mm; Manufacturer_Part_Number: CC0402JRNPO9BN100; Manufacturer: YAGEO; Part_Preference: Recommended; ECCN_US: EAR99; ECCN_EU: NEC; Provided_By: SUBCO; Component_Country_Of_Origin: China; ID: 2465; Order_Code_RS: 3019160RL; ShowFields: YES
CN23 = MCD-01992: FFC et FPC connector 0.5MM 40P LNG MTL FITNG SMT VERT MNT; Manufacturer_Part_Number: FH52E-40S-05SH; Manufacturer: HIROSE; Part_Preference: Recommended; ECCN_US: EAR99; ECCN_EU: NEC; Provided_By: SUBCO; Component_Country_Of_Origin: Japan; ID: 4092; ShowFields: YES
CN30 = MCD-00610: Surface mount, vertical male connector. Double row of 5 pins, 1.27mm pitch, 3.05mm lead. Mates with FFSD connector; Manufacturer_Part_Number: FTSH-105-01-L-DV-K; Manufacturer: SAMTEC; Alternate_Manufacturer_Part_Number: P127B-2x05MGF-079-1A; Alternate_Manufacturer: JIUBABA; Part_Preference: Recommended; Provided_By: SUBCO; Component_Country_Of_Origin: China, Costa Rica, Malaysia, USA, Vietnam; ID: 3134; Order_Code_RS: 159-2365; ShowFields: YES
H1-H6 = MCD-00035: POSITION HOLE C6D3R5; Part_Type: Misc; Part_Preference: Recommended; Component_Country_Of_Origin: Unknown; ID: 2482; ShowFields: YES
HW9 = MCD-00612: FFSD series Ribbon cable pitch1.27mm 5pin x 2row, 15cm length.; Part_Type: Misc; Manufacturer: SAMTEC; Part_Preference: Recommended; ECCN_US: EAR99; ECCN_EU: NEC; Provided_By: SUBCO; Component_Country_Of_Origin: China, Costa Rica, Malaysia, USA, Vietnam; ID: 3133; Order_Code_RS: 901-1683; ShowFields: YES
HW13 HW14 HW16 HW17 = MCD-01711: Screw, M3, 8 mm, Stainless Steel; Part_Type: Accessory; Manufacturer: ETTINGER; Part_Preference: Forbidden; Provided_By: SUBCO; Component_Country_Of_Origin: Unknown; ID: 3811; ShowFields: YES
HW15 HW18 HW54 HW68 = MCD-01710: M3 2x12.5mm male to female Hinged Hex Standoff made of brass with nickel plated finish; Part_Type: Accessory; Manufacturer: ETTINGER; Alternate_Manufacturer_Part_Number: 14.04.3.00034; Alternate_Manufacturer: JIUBABA; Part_Preference: Forbidden; Provided_By: SUBCO; Component_Country_Of_Origin: Unknown; ID: 3810; ShowFields: YES
HW19 HW20 = MCD-01841: Nylon Pillar M3 x 31.75mm Male/Female; Part_Type: Accessory; Manufacturer_Part_Number: 4820; Manufacturer: KEYSTONE ELECTRONICS; Part_Preference: Forbidden; ECCN_US: EAR99; ECCN_EU: NEC; Provided_By: SUBCO; Component_Country_Of_Origin: USA; ID: 3941; ShowFields: YES
HW22 HW26 HW69 HW70 = MCD-01354: Nut, Steel, M3; Part_Type: Accessory; Manufacturer_Part_Number: 1110030; Manufacturer: DURATOOL; Manufacturer_HQ_COO: Unknown; Part_Preference: Forbidden; Component_Country_Of_Origin: Germany; ID: 3454; ShowFields: YES
HW40 = MCD-01035: MB1370 - LCD WVGA 7 inches daughter board; Part_Type: Misc; Manufacturer: STMICROELECTRONICS; Manufacturer_HQ_COO: EU; Part_Preference: Recommended; Provided_By: SUBCO with ST control; Component_Country_Of_Origin: Unknown; ID: 2986; ShowFields: YES
HW44 = MCD-02049: FFC/FPC Flex Cable, Opposite Side Contacts, WR-FFC 0.5mm Type 2 40P 100mm length, customized with EMI shielding; Part_Type: Accessory; Manufacturer: WURTH ELEKTRONIK; Part_Preference: Recommended; Order_Code_RS: 1222740; ECCN_US: EAR99; ECCN_EU: NEC; Provided_By: SUBCO; Component_Country_Of_Origin: China; ID: 4149; ShowFields: YES
R125 R126 R155 R156 R285 = MCD-00056: as R138 on sheet Audio_Codec
R159 = MCD-00593: Ferrite bead, 600R @ 100MHz,  1.3A, 150mOhm, 0603; Manufacturer_Part_Number: BLM18KG601SN1D; Manufacturer: MURATA; Part_Preference: Recommended; ECCN_US: EAR99; ECCN_EU: NEC; Provided_By: SUBCO; Component_Country_Of_Origin: Japan°°; ID: 3152; Order_Code_RS: 167-4203; ShowFields: YES

## Sheet JTAG&Trace.SchDoc: JTAG & Trace
size A4; Date: Not used; ApprovedBy: Not used; CheckedBy: Not used; Author: Not used; CompanyName: STMicroelectronics; DrawnBy: Not used; Engineer: Not used; Organization: Not used; Address1: Not used; Address2: Not used; Address3: Not used; Address4: Not used; DocumentNumber: Not used; Revision: Not used; SheetNumber: 22; SheetTotal: 23
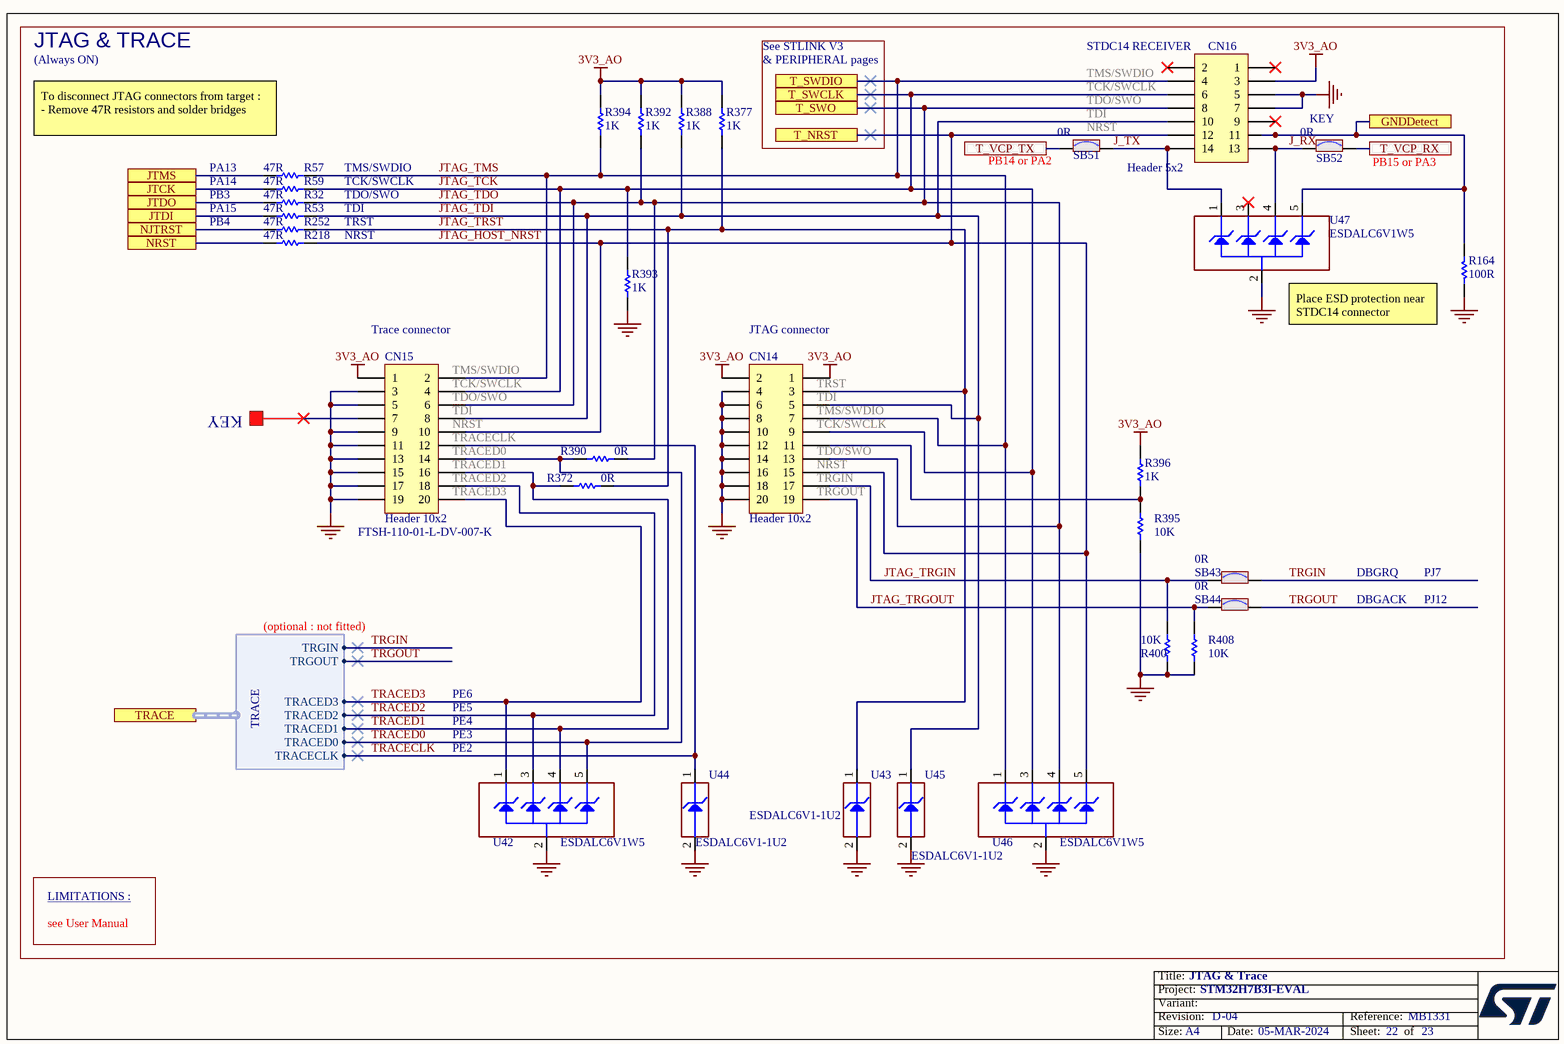
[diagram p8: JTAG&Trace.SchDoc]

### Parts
CN14  Header 10x2  [CON_CVILUX_CH87-20-2-V-1-00]
CN15  Header 10x2  [CON_SAMTEC_FTSH-110-01-L-DV]
CN16  value Header 5x2  [CON_STDC14_Receiver_MEDIUM_WITH_MIPI10_3D]  (hidden comment: Header 7x2)
R32  value 47R  [R0603]  (hidden comment: Resistor)
R53  value 47R  [R0603]  (hidden comment: Resistor)
R57  value 47R  [R0603]  (hidden comment: Resistor)
R59  value 47R  [R0603]  (hidden comment: Resistor)
R164  value 100R  [R0402]  (hidden comment: Resistor)
R218  value 47R  [R0603]  (hidden comment: Resistor)
R252  value 47R  [R0603]  (hidden comment: Resistor)
R372  value 0R  [R0402]  (hidden comment: Resistor)
R377  value 1K  [R0402]  (hidden comment: Resistor)
R388  value 1K  [R0402]  (hidden comment: Resistor)
R390  value 0R  [R0402]  (hidden comment: Resistor)
R392  value 1K  [R0402]  (hidden comment: Resistor)
R393  value 1K  [R0402]  (hidden comment: Resistor)
R394  value 1K  [R0402]  (hidden comment: Resistor)
R395  value 10K  [R0402]  (hidden comment: Resistor)
R396  value 1K  [R0402]  (hidden comment: Resistor)
R400  value 10K  [R0402]  (hidden comment: Resistor)
R408  value 10K  [R0402]  (hidden comment: Resistor)
SB43  value 0R  [SOLDER-BRIDGE_R0603-0R]  (hidden comment: SB_ON)
SB44  value 0R  [SOLDER-BRIDGE_R0603-0R]  (hidden comment: SB_ON)
SB51  value 0R  [SOLDER-BRIDGE_R0402-0R]  (hidden comment: SB_ON)
SB52  value 0R  [SOLDER-BRIDGE_R0402-0R]  (hidden comment: SB_ON)
U42  ESDALC6V1W5  [ESD_SOT323-5L]
U43  value ESDALC6V1-1U2  [ESD_ST0201]  (hidden comment: ESD-TRANSIL)
U44  value ESDALC6V1-1U2  [ESD_ST0201]  (hidden comment: ESD-TRANSIL)
U45  value ESDALC6V1-1U2  [ESD_ST0201]  (hidden comment: ESD-TRANSIL)
U46  ESDALC6V1W5  [ESD_SOT323-5L]
U47  ESDALC6V1W5  [ESD_SOT323-5L]

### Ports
GNDDetect, JTCK, JTDI, JTDO, JTMS, NJTRST, NRST, T_NRST, T_SWCLK, T_SWDIO, T_SWO, T_VCP_RX, T_VCP_TX, TRACE (harness TRACE)

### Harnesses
TRACE: TRACECLK, TRACED0, TRACED1, TRACED2, TRACED3, TRGIN, TRGOUT

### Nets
3V3_AO: CN14.1 CN14.2 CN15.1 CN16.3 R377.2 R388.2 R392.2 R394.2 R396.2
GND: CN14.4 CN14.6 CN14.8 CN14.10 CN14.12 CN14.14 CN14.16 CN14.18 CN14.20 CN15.3 CN15.5 CN15.9 CN15.11 CN15.13 CN15.15 CN15.17 CN15.19 CN16.5 CN16.7 R164.1 R393.1 R395.1 R400.1 R408.1 U42.2(GND) U43.2(GND) U44.2(GND) U45.2(GND) U46.2(GND) U47.2(GND)
GNDDetect: CN16.11 R164.2 U47.5(IO4) ; port GNDDetect
J_RX: CN16.13 SB52.1 U47.4(IO3)
J_TX: CN16.14 SB51.2 U47.1(IO1)
JTAG_HOST_NRST: CN14.15 CN15.10 CN16.12 R218.1 U46.5(IO4) ; port T_NRST
JTAG_TCK: CN14.9 CN15.4 CN16.6 R59.1 R393.2 U46.3(IO2) ; port T_SWCLK
JTAG_TDI: CN14.5 CN15.8 CN16.10 R53.1 R388.1 U45.1(IO1)
JTAG_TDO: CN14.13 CN15.6 CN16.8 R32.1 R390.2 R392.1 U46.4(IO3) ; port T_SWO
JTAG_TMS: CN14.7 CN15.2 CN16.4 R57.1 R394.1 U46.1(IO1) ; port T_SWDIO
JTAG_TRGIN: CN14.17 R400.2 SB43.1
JTAG_TRGOUT: CN14.19 R408.2 SB44.1
JTAG_TRST: CN14.3 R252.1 R372.2 R377.1 U43.1(IO1)
NJTRST: R252.2 ; port NJTRST
NRST: R218.2 ; port NRST
PA13: R57.2 ; port JTMS
PA14: R59.2 ; port JTCK
PA15: R53.2 ; port JTDI
PB3: R32.2 ; port JTDO
T_VCP_RX: SB52.2 ; port T_VCP_RX
T_VCP_TX: SB51.1 ; port T_VCP_TX
TRACECLK: CN15.12 U44.1(IO1) ; port TRACE.TRACECLK
TRACED0: CN15.14 R390.1 U42.5(IO4) ; port TRACE.TRACED0
TRACED1: CN15.16 R372.1 U42.4(IO3) ; port TRACE.TRACED1
TRACED2: CN15.18 U42.3(IO2) ; port TRACE.TRACED2
TRACED3: CN15.20 U42.1(IO1) ; port TRACE.TRACED3
TRGIN: SB43.2 ; port TRACE.TRGIN
TRGOUT: SB44.2 ; port TRACE.TRGOUT
NetCN14_11: CN14.11 R395.2 R396.1

Not connected (* = marked no-connect by the designer): CN15 7*; CN16 1* 2* 9*; U47 3(IO2)*

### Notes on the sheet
- JTAG & TRACE
- See STLINK V3
- (near CN16) STDC14 RECEIVER
- (Always ON)
- & PERIPHERAL pages
- TMS/SWDIO
- TCK/SWCLK
- (near SB51) TDO/SWO
- (near SB51) TDI
- (near SB52) KEY
- To disconnect JTAG connectors from target :
  - Remove 47R resistors and solder bridges
- PA13
- PA14
- (near SB51) PB14 or PA2
- (near SB51) NRST
- (near SB52) PB15 or PA3
- PB3
- PA15
- PB4
- TDO/SWO
- TDI
- TRST
- NRST
- (near U47) Place ESD protection near STDC14 connector
- (near CN15) Trace connector
- (near CN15) TMS/SWDIO
- (near CN15) TCK/SWCLK
- (near CN14) JTAG connector
- (near CN14) TRST
- KEY
- (near CN15) TDO/SWO
- (near CN15) TDI
- (near CN15) NRST
- (near CN15) TRACECLK
- (near CN15) TRACED0
- (near CN14) TDI
- (near CN14) TMS/SWDIO
- (near CN14) TCK/SWCLK
- (near CN14) TDO/SWO
- (near CN15) TRACED1
- (near CN15) TRACED2
- (near CN15) TRACED3
- (near CN14) NRST
- (near CN14) TRGIN
- (near CN14) TRGOUT
- (near CN15) FTSH-110-01-L-DV-007-K
- DBGRQ
- PJ7
- (optional : not fitted)
- DBGACK
- PJ12
- PE6
- PE5
- PE4
- PE3
- (near U42) PE2
- LIMITATIONS :
- see User Manual

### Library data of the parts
CN14 = MCD-01058: Header, 2.54mm, 10x2, VR, TH, Height 9.1mm/3,1mm; Part_Type: Connector; Manufacturer_Part_Number: TST-110-01-G-D; Manufacturer: SAMTEC; Alternate_Manufacturer_Part_Number: CH87-20-2-V-1-00; Alternate_Manufacturer: CVILUX; Part_Preference: Recommended; Provided_By: SUBCO; Component_Country_Of_Origin: China, Costa Rica, Malaysia, USA, Vietnam; ID: 2964; Order_Code_RS: 155-5306; ShowFields: YES
CN15 = MCD-00557: Header 10x2, 1.27mm, VR, CMS, Height 3.05mm; Part_Type: Connector; Manufacturer_Part_Number: FTSH-110-01-L-DV; Manufacturer: SAMTEC; Alternate_Manufacturer_Part_Number: P127B-2*10MGF-079-1E7A; Alternate_Manufacturer: JIUBABA; BMS_Part_Number: 9183690; Part_Preference: Recommended; Provided_By: SUBCO; Component_Country_Of_Origin: China, Costa Rica, Malaysia, USA, Vietnam; ID: 3188; Order_Code_RS: 767-6774; ShowFields: YES
CN16 = MCD-01226: Header 5x2, 1.27mm, Dual row, Straight, Surface mount, vertical male connector. 3.05mm lead. Mates with FFSD connector. Footprint compatible with FTSH-107-01-L-DV,-K,-A,-P,-ES (STDC14 MEDIUM); Manufacturer_Part_Number: FTSH-105-01-L-DV-K; Manufacturer: SAMTEC; Alternate_Manufacturer_Part_Number: P127B-2x05MGF-079-1A; Alternate_Manufacturer: JIUBABA; Part_Preference: Recommended; Partial_Alternate_Internal_Part_Number: MCD-02956, MCD-03788; Provided_By: SUBCO; Component_Country_Of_Origin: China, Costa Rica, Malaysia, USA, Vietnam; ID: 3265; Order_Code_RS: 159-2332; ShowFields: YES
R32 R53 R57 R59 R218 R252 = MCD-00482: Resistor,47R,0603,1%,1/10W; Manufacturer_Part_Number: RC0603FR-0747RL; Manufacturer: YAGEO; Part_Preference: Recommended; Provided_By: SUBCO; ECCN_US: EAR99; ECCN_EU: NEC; Component_Country_Of_Origin: China; ID: 2795; ShowFields: YES
R164 = MCD-00067: as R417 on sheet Audio_Codec
R372 R390 = MCD-00052: as R135-R137 on sheet Audio_Codec
R377 R388 R392-R394 R396 = MCD-00061: Resistor,1K,0402,1%,1/16W; Manufacturer_Part_Number: RC0402FR-071KL; Manufacturer: YAGEO; Part_Preference: Recommended; Provided_By: SUBCO; ECCN_US: EAR99; ECCN_EU: NEC; Component_Country_Of_Origin: China; ID: 2532; Order_Code_RS: 9239235; ShowFields: YES
R395 R400 R408 = MCD-00053: as R402 on sheet Audio_Codec
SB43 SB44 = MCD-00071: as SB25-SB28 on sheet Audio_Codec
SB51 SB52 = MCD-01618: Solder Bridge 0402 ON; Part_Type: Resistor; Manufacturer_Part_Number: RC0402JR-070RL; Manufacturer: YAGEO; Part_Preference: Recommended; Provided_By: SUBCO; Component_Country_Of_Origin: China; ID: 3718; Order_Code_RS: 618-5804; ShowFields: YES
U42 U46 = MCD-00136: Dual Transil array for ESD protection; Manufacturer: STMICROELECTRONICS; Part_Type: Diode; BMS_Part_Number: 9151112; Manufacturer_HQ_COO: EU; Part_Preference: Recommended; Provided_By: SUBCO with ST control; ECCN_US: EAR99; ECCN_EU: NEC; Component_Country_Of_Origin: China; ID: 2731; Order_Code_RS: 178-7373; ShowFields: YES
U43-U45 = MCD-00170: ESD protection 6V1; Part_Type: Diode; Manufacturer: STMICROELECTRONICS; BMS_Part_Number: 9151132; Manufacturer_HQ_COO: EU; Part_Preference: Recommended; Provided_By: SUBCO with ST control; ECCN_US: EAR99; ECCN_EU: NEC; Component_Country_Of_Origin: China; ID: 2696; Order_Code_RS: 795-8404; ShowFields: YES
U47 = MCD-00136: Dual Transil array for ESD protection; Part_Type: Diode; Manufacturer: STMICROELECTRONICS; BMS_Part_Number: 9151112; Manufacturer_HQ_COO: EU; Part_Preference: Recommended; Provided_By: SUBCO with ST control; ECCN_US: EAR99; ECCN_EU: NEC; Component_Country_Of_Origin: China; ID: 2731; Order_Code_RS: 178-7373; ShowFields: YES

## Sheet MCU_Clock&Reset.SchDoc: MCU Clocks and Reset
size A4; Date: Not used; ApprovedBy: Not used; CheckedBy: Not used; Author: Not used; CompanyName: STMicroelectronics; DrawnBy: Not used; Engineer: Not used; Organization: Not used; Address1: Not used; Address2: Not used; Address3: Not used; Address4: Not used; DocumentNumber: Not used; Revision: Not used; SheetNumber: 4; SheetTotal: 23
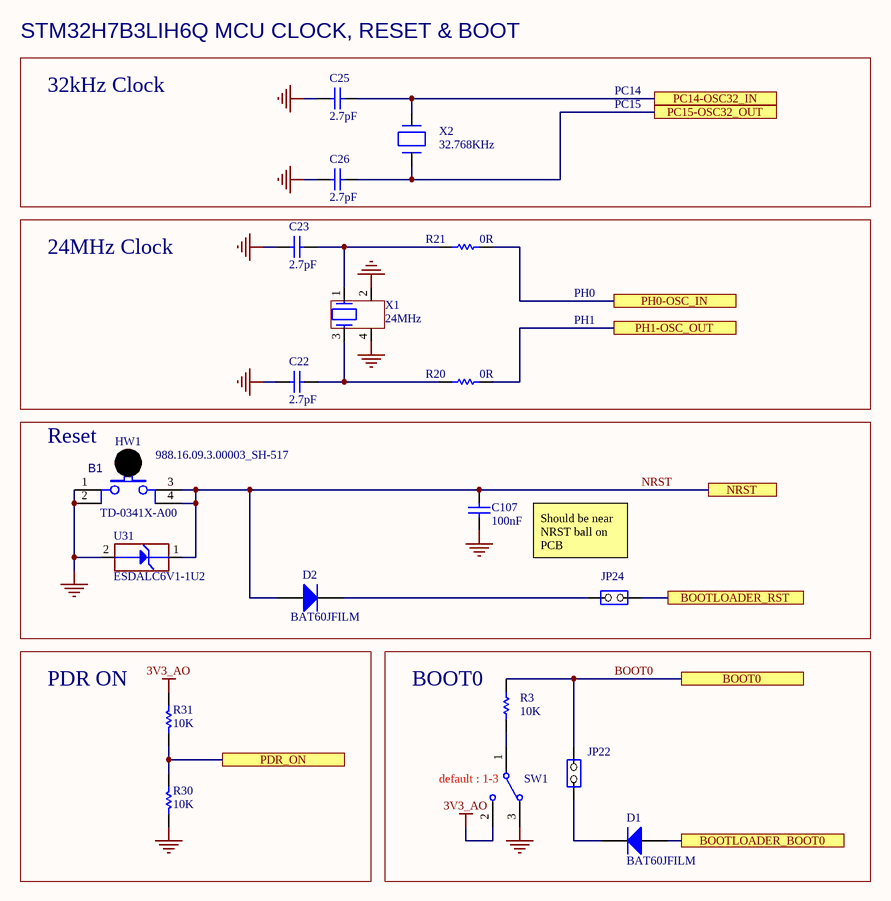
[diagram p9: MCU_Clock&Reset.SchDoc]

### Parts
B1  value TD-0341X-A00  [SWI_WEALTHMETAL_TD-0341_4P_BLACK]  (hidden comment: SW-PUSH-CMS)
C22  value 2.7pF  [C0603]  (hidden comment: Capacitor)
C23  value 2.7pF  [C0603]  (hidden comment: Capacitor)
C25  value 2.7pF  [C0603]  (hidden comment: Capacitor)
C26  value 2.7pF  [C0603]  (hidden comment: Capacitor)
C107  value 100nF  [C0402]  (hidden comment: Capacitor)
D1  BAT60JFILM  [DIO_SOD323]
D2  BAT60JFILM  [DIO_SOD323]
HW1  value 988.16.09.3.00003_SH-517  (hidden comment: BUTTON_HAT_BLACK)  (mechanical)
JP22  Jumper_Header 2x1  [CON_SAMTEC_TSW-102-07-G-S]  (value not drawn)
JP24  Jumper_Header 2x1  [CON_SAMTEC_TSW-102-07-G-S]  (value not drawn)
R3  value 10K  [R0402]  (hidden comment: Resistor)
R20  value 0R  [R0402]  (hidden comment: Resistor)
R21  value 0R  [R0402]  (hidden comment: Resistor)
R30  value 10K  [R0402]  (hidden comment: Resistor)
R31  value 10K  [R0402]  (hidden comment: Resistor)
SW1  SW_MECA_1K2  [SWI_EAO_09-03290-01_EXTENDED_STRAIGHT_BLACK]  (value not drawn)
U31  value ESDALC6V1-1U2  [ESD_ST0201]  (hidden comment: ESD-TRANSIL)
X1  value 24MHz  [CRY_NX2016SA_4P]  (hidden comment: XTAL_4_PINS)
X2  value 32.768KHz  [CRY_NX3215SA_2P]  (hidden comment: XTAL_2_PINS)

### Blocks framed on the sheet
24MHz Clock: C22 C23 R20 R21 X1
Reset: B1 C107 D2 HW1 JP24 U31
PDR ON: R30 R31
BOOT0: D1 JP22 R3 SW1

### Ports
BOOT0, BOOTLOADER_BOOT0, BOOTLOADER_RST, NRST, PC14-OSC32_IN, PC15-OSC32_OUT, PDR_ON, PH0-OSC_IN, PH1-OSC_OUT

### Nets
3V3_AO: R31.1 SW1.2
GND: B1.1 B1.2 C22.1 C23.1 C25.1 C26.1 C107.1 R30.2 SW1.3 U31.2(GND) X1.2 X1.4
BOOT0: JP22.2(NO) R3.1 ; port BOOT0
BOOTLOADER_BOOT0: D1.1(A) ; port BOOTLOADER_BOOT0
BOOTLOADER_RST: JP24.2(NO) ; port BOOTLOADER_RST
NRST: B1.3 B1.4 C107.2 D2.1(A) U31.1(IO1) ; port NRST
PC14-OSC32_IN: C25.2 X2.2(X2) ; port PC14-OSC32_IN
PC15-OSC32_OUT: C26.2 X2.1(X1) ; port PC15-OSC32_OUT
PDR_ON: R30.1 R31.2 ; port PDR_ON
PH0: R21.2 ; port PH0-OSC_IN
PH1: R20.2 ; port PH1-OSC_OUT
NetC22_2: C22.2 R20.1 X1.3
NetC23_2: C23.2 R21.1 X1.1
NetD1_2: D1.2(K) JP22.1(COMMON)
NetD2_2: D2.2(K) JP24.1(COMMON)
NetR3_2: R3.2 SW1.1

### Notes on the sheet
- STM32H7B3LIH6Q MCU CLOCK, RESET & BOOT
- 32kHz Clock
- PC14
- PC15
- PH0
- PH1
- Should be near NRST ball on PCB
- (near SW1) default : 1-3

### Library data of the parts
B1 = MCD-00001: Non-Open Push-Button 0.1A 24V BLACK; Manufacturer: WEALTHMETAL; Part_Type: Misc; Part_Preference: Not recommended; Partial_Alternate_Internal_Part_Number: MCD-03587; Provided_By: SUBCO; Alternate_EMS: A; Component_Country_Of_Origin: Unknown; ID: 2463; ShowFields: YES
C22 C23 C25 C26 = MCD-01726: Capacitor, MLCC, 2.7pF, 50V, NPO, -+0.25pF 0603; Manufacturer_Part_Number: CC0603CRNPO9BN2R7; Manufacturer: YAGEO; Part_Preference: Recommended; Provided_By: SUBCO; Component_Country_Of_Origin: China; ID: 3826; Order_Code_RS: 616-9155; ShowFields: YES
C107 = MCD-00006: as C56 on sheet Audio_Codec
D1 D2 = MCD-00034: Manufacturer: STMICROELECTRONICS; Part_Type: Diode; BMS_Part_Number: 9151097; Manufacturer_HQ_COO: EU; Part_Preference: Recommended; Provided_By: SUBCO with ST control; ECCN_US: EAR99; ECCN_EU: NEC; Component_Country_Of_Origin: China; ID: 2483; Order_Code_RS: 714-6879; ShowFields: YES
HW1 = MCD-00635: Black Hat for switch TD0341X-G01-BLA; Part_Type: Mechanical; Manufacturer: JIUBABA; Part_Preference: Alternate; Provided_By: SUBCO; Alternate_EMS: A; Component_Country_Of_Origin: Unknown; ID: 3106; ShowFields: YES
JP22 JP24 = MCD-00045: Header, 2x1, 2,54mm, VR, TH, Height 5.84mm/2.54mm; Manufacturer_Part_Number: TSW-102-07-G-S; Manufacturer: SAMTEC; Part_Type: Connector; Alternate_Manufacturer_Part_Number: 313102S111116;313102S111116; Alternate_Manufacturer: JIUBABA; LIANYI; Full_Alternate_Internal_Part_Number: MCD-02390; Part_Preference: Recommended; Partial_Alternate_Internal_Part_Number: MCD-02957, MCD-03720; Provided_By: SUBCO; Component_Country_Of_Origin: China, Costa Rica, Malaysia, USA, Vietnam; ID: 2545; Order_Code_RS: 2505044; ShowFields: YES
R3 R30 R31 = MCD-00053: as R402 on sheet Audio_Codec
R20 R21 = MCD-00052: as R135-R137 on sheet Audio_Codec
SW1 = MCD-00566: Mechanical Slide Switches 1K2 BLK ACT GOLD STRT MNT; Part_Type: Misc; Manufacturer: EAO; Part_Preference: Recommended; Value: 09.03290.01; Provided_By: SUBCO; Component_Country_Of_Origin: Switzerland°°; ID: 3181; Order_Code_RS: 204-7865; ShowFields: YES
U31 = MCD-00170: as U43 on sheet JTAG&Trace
X1 = MCD-01036: Crystal 24MHz, 6pF, +-20ppm, 80ohms max, SMD; Part_Type: Crystal_Osc; Manufacturer_Part_Number: NX2016SA-24MHZ-EXS00A-CS10820; Manufacturer: NDK; BMS_Part_Number: 9157045; Part_Preference: Recommended; Provided_By: SUBCO; ECCN_US: EAR99; ECCN_EU: NEC; Component_Country_Of_Origin: Unknown; ID: 2989; ShowFields: YES
X2 = MCD-00091: Crystal 32.768kHz, 6pF, +-20ppm, 50Kohms max, SMD; Part_Type: Crystal_Osc; Manufacturer_Part_Number: NX3215SA-32.768KHZ-EXS00A-MU00525; Manufacturer: NDK; BMS_Part_Number: 9157034; Part_Preference: Recommended; Provided_By: SUBCO; ECCN_US: EAR99; ECCN_EU: NEC; Component_Country_Of_Origin: Unknown; ID: 2553; ShowFields: YES

## Sheet Memory.SchDoc: Memory
size A4; Date: Not used; ApprovedBy: Not used; CheckedBy: Not used; Author: Not used; CompanyName: STMicroelectronics; DrawnBy: Not used; Engineer: Not used; Organization: Not used; Address1: Not used; Address2: Not used; Address3: Not used; Address4: Not used; DocumentNumber: Not used; Revision: Not used; SheetNumber: 7; SheetTotal: 23
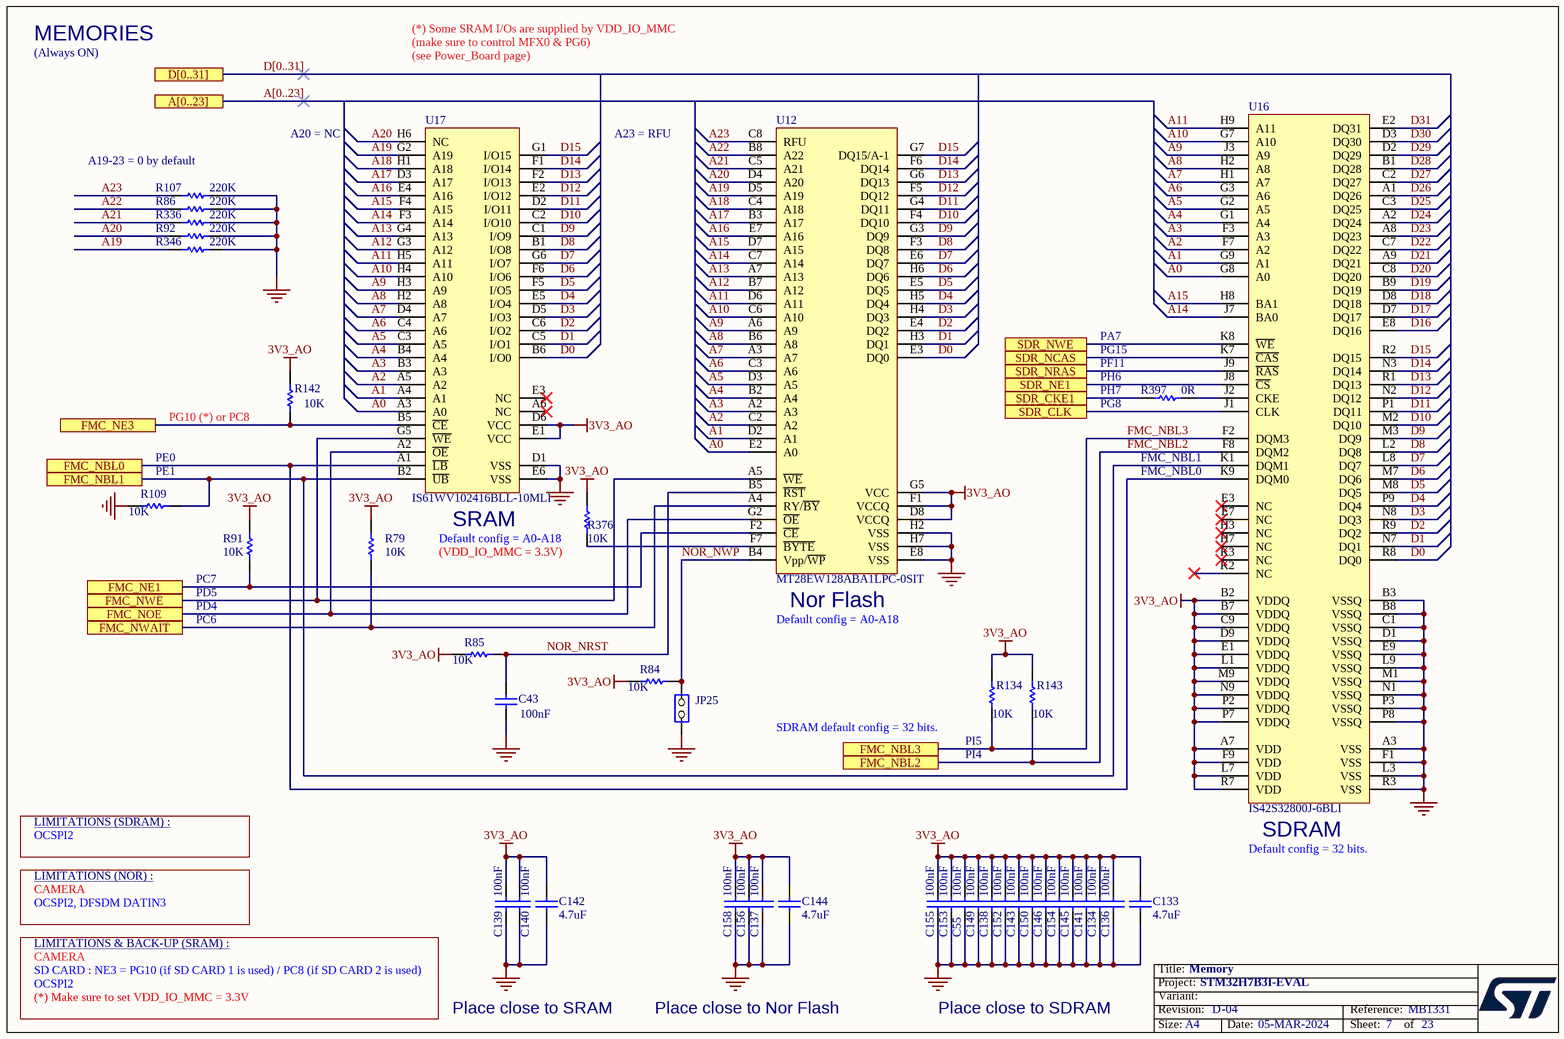
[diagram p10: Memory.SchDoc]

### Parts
C43  value 100nF  [C0402]  (hidden comment: Capacitor)
C55  value 100nF  [C0402]  (hidden comment: Capacitor)
C133  value 4.7uF  [C0603]  (hidden comment: Capacitor)
C134  value 100nF  [C0402]  (hidden comment: Capacitor)
C136  value 100nF  [C0402]  (hidden comment: Capacitor)
C137  value 100nF  [C0402]  (hidden comment: Capacitor)
C138  value 100nF  [C0402]  (hidden comment: Capacitor)
C139  value 100nF  [C0402]  (hidden comment: Capacitor)
C140  value 100nF  [C0402]  (hidden comment: Capacitor)
C141  value 100nF  [C0402]  (hidden comment: Capacitor)
C142  value 4.7uF  [C0603]  (hidden comment: Capacitor)
C143  value 100nF  [C0402]  (hidden comment: Capacitor)
C144  value 4.7uF  [C0603]  (hidden comment: Capacitor)
C145  value 100nF  [C0402]  (hidden comment: Capacitor)
C146  value 100nF  [C0402]  (hidden comment: Capacitor)
C149  value 100nF  [C0402]  (hidden comment: Capacitor)
C150  value 100nF  [C0402]  (hidden comment: Capacitor)
C152  value 100nF  [C0402]  (hidden comment: Capacitor)
C153  value 100nF  [C0402]  (hidden comment: Capacitor)
C154  value 100nF  [C0402]  (hidden comment: Capacitor)
C155  value 100nF  [C0402]  (hidden comment: Capacitor)
C156  value 100nF  [C0402]  (hidden comment: Capacitor)
C158  value 100nF  [C0402]  (hidden comment: Capacitor)
JP25  Jumper_Header 2x1  [CON_SAMTEC_TSW-102-07-G-S]  (value not drawn)
R79  value 10K  [R0402]  (hidden comment: Resistor)
R84  value 10K  [R0402]  (hidden comment: Resistor)
R85  value 10K  [R0402]  (hidden comment: Resistor)
R86  value 220K  [R0402]  (hidden comment: Resistor)
R91  value 10K  [R0402]  (hidden comment: Resistor)
R92  value 220K  [R0402]  (hidden comment: Resistor)
R107  value 220K  [R0402]  (hidden comment: Resistor)
R109  value 10K  [R0402]  (hidden comment: Resistor)
R134  value 10K  [R0402]  (hidden comment: Resistor)
R142  value 10K  [R0402]  (hidden comment: Resistor)
R143  value 10K  [R0402]  (hidden comment: Resistor)
R336  value 220K  [R0402]  (hidden comment: Resistor)
R346  value 220K  [R0402]  (hidden comment: Resistor)
R376  value 10K  [R0402]  (hidden comment: Resistor)
R397  value 0R  [R0402]  (hidden comment: Resistor)
U12  value MT28EW128ABA1LPC-0SIT  [ICC_FBGA64_11X13_P1]  (hidden comment: PC28F128M29EWLA)
U16  value IS42S32800J-6BLI  [ICC_TFBGA90_8X13_P080]  (hidden comment: IS42S32800G-6BLI)
U17  IS61WV102416BLL-10MLI  [ICC_MINI-BGA48_9X11_P075]

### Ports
A[0..23], D[0..31], FMC_NBL0, FMC_NBL1, FMC_NBL2, FMC_NBL3, FMC_NE1, FMC_NE3, FMC_NOE, FMC_NWAIT, FMC_NWE, SDR_CKE1, SDR_CLK, SDR_NCAS, SDR_NE1, SDR_NRAS, SDR_NWE

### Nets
3V3_AO: C55.1 C133.2 C134.1 C136.1 C137.1 C138.1 C139.1 C140.1 C141.1 C142.2 C143.1 C144.2 C145.1 C146.1 C149.1 C150.1 C152.1 C153.1 C154.1 C155.1 C156.1 C158.1 R79.2 R84.2 R85.1 R91.2 R134.2 R142.2 R143.2 R376.2 U12.D8(VCCQ) U12.F1(VCCQ) U12.G5(VCC) U16.A7(VDD) U16.B2(VDDQ) U16.B7(VDDQ) U16.C9(VDDQ) U16.D9(VDDQ) U16.E1(VDDQ) U16.F9(VDD) U16.L1(VDDQ) U16.L7(VDD) U16.M9(VDDQ) U16.N9(VDDQ) U16.P2(VDDQ) U16.P7(VDDQ) U16.R7(VDD) U17.D6(VCC) U17.E1(VCC)
GND: C43.2 C55.2 C133.1 C134.2 C136.2 C137.2 C138.2 C139.2 C140.2 C141.2 C142.1 C143.2 C144.1 C145.2 C146.2 C149.2 C150.2 C152.2 C153.2 C154.2 C155.2 C156.2 C158.2 JP25.1(COMMON) R86.1 R92.1 R107.1 R109.1 R336.1 R346.1 U12.E8(VSS) U12.H2(VSS) U12.H7(VSS) U16.A3(VSS) U16.B3(VSSQ) U16.B8(VSSQ) U16.C1(VSSQ) U16.D1(VSSQ) U16.E9(VSSQ) U16.F1(VSS) U16.L3(VSS) U16.L9(VSSQ) U16.M1(VSSQ) U16.N1(VSSQ) U16.P3(VSSQ) U16.P8(VSSQ) U16.R3(VSS) U17.D1(VSS) U17.E6(VSS)
A0: U12.E2(A0) U16.G8(A0) U17.A3(A0)
A1: U12.D2(A1) U16.G9(A1) U17.A4(A1)
A2: U12.C2(A2) U16.F7(A2) U17.A5(A2)
A3: U12.A2(A3) U16.F3(A3) U17.B3(A3)
A4: U12.B2(A4) U16.G1(A4) U17.B4(A4)
A5: U12.D3(A5) U16.G2(A5) U17.C3(A5)
A6: U12.C3(A6) U16.G3(A6) U17.C4(A6)
A7: U12.A3(A7) U16.H1(A7) U17.D4(A7)
A8: U12.B6(A8) U16.H2(A8) U17.H2(A8)
A9: U12.A6(A9) U16.J3(A9) U17.H3(A9)
A10: U12.C6(A10) U16.G7(A10) U17.H4(A10)
A11: U12.D6(A11) U16.H9(A11) U17.H5(A11)
A12: U12.B7(A12) U17.G3(A12)
A13: U12.A7(A13) U17.G4(A13)
A14: U12.C7(A14) U16.J7(BA0) U17.F3(A14)
A15: U12.D7(A15) U16.H8(BA1) U17.F4(A15)
A16: U12.E7(A16) U17.E4(A16)
A17: U12.B3(A17) U17.D3(A17)
A18: U12.C4(A18) U17.H1(A18)
A19: R346.2 U12.D5(A19) U17.G2(A19)
A20: R92.2 U12.D4(A20) U17.H6(NC)
A21: R336.2 U12.C5(A21)
A22: R86.2 U12.B8(A22)
A23: R107.2 U12.C8(RFU)
D0: U12.E3(DQ0) U16.R8(DQ0) U17.B6(I/O0)
D1: U12.H3(DQ1) U16.N7(DQ1) U17.C5(I/O1)
D2: U12.E4(DQ2) U16.R9(DQ2) U17.C6(I/O2)
D3: U12.H4(DQ3) U16.N8(DQ3) U17.D5(I/O3)
D4: U12.H5(DQ4) U16.P9(DQ4) U17.E5(I/O4)
D5: U12.E5(DQ5) U16.M8(DQ5) U17.F5(I/O5)
D6: U12.H6(DQ6) U16.M7(DQ6) U17.F6(I/O6)
D7: U12.E6(DQ7) U16.L8(DQ7) U17.G6(I/O7)
D8: U12.F3(DQ8) U16.L2(DQ8) U17.B1(I/O8)
D9: U12.G3(DQ9) U16.M3(DQ9) U17.C1(I/O9)
D10: U12.F4(DQ10) U16.M2(DQ10) U17.C2(I/O10)
D11: U12.G4(DQ11) U16.P1(DQ11) U17.D2(I/O11)
D12: U12.F5(DQ12) U16.N2(DQ12) U17.E2(I/O12)
D13: U12.G6(DQ13) U16.R1(DQ13) U17.F2(I/O13)
D14: U12.F6(DQ14) U16.N3(DQ14) U17.F1(I/O14)
D15: U12.G7(DQ15/A-1) U16.R2(DQ15) U17.G1(I/O15)
D16: U16.E8(DQ16)
D17: U16.D7(DQ17)
D18: U16.D8(DQ18)
D19: U16.B9(DQ19)
D20: U16.C8(DQ20)
D21: U16.A9(DQ21)
D22: U16.C7(DQ22)
D23: U16.A8(DQ23)
D24: U16.A2(DQ24)
D25: U16.C3(DQ25)
D26: U16.A1(DQ26)
D27: U16.C2(DQ27)
D28: U16.B1(DQ28)
D29: U16.D2(DQ29)
D30: U16.D3(DQ30)
D31: U16.E2(DQ31)
FMC_NBL0: U16.K9(DQM0) U17.A1(~{LB}) ; port FMC_NBL0
FMC_NBL1: R109.2 U16.K1(DQM1) U17.B2(~{UB}) ; port FMC_NBL1
FMC_NBL2: R143.1 U16.F8(DQM2) ; port FMC_NBL2
FMC_NBL3: R134.1 U16.F2(DQM3) ; port FMC_NBL3
FMC_NE1: R91.1 U12.F2(~{CE}) ; port FMC_NE1
FMC_NE3: R142.1 U17.B5(~{CE}) ; port FMC_NE3
FMC_NOE: U12.G2(~{OE}) U17.A2(~{OE}) ; port FMC_NOE
FMC_NWAIT: R79.1 U12.A4(RY/~{BY}) ; port FMC_NWAIT
FMC_NWE: U12.A5(~{WE}) U17.G5(~{WE}) ; port FMC_NWE
NOR_NRST: C43.1 R85.2 U12.B5(~{RST})
NOR_NWP: JP25.2(NO) R84.1 U12.B4(Vpp/~{WP})
SDR_CKE1: R397.1 ; port SDR_CKE1
SDR_CLK: U16.J1(CLK) ; port SDR_CLK
SDR_NCAS: U16.K7(~{CAS}) ; port SDR_NCAS
SDR_NE1: U16.J8(~{CS}) ; port SDR_NE1
SDR_NRAS: U16.J9(~{RAS}) ; port SDR_NRAS
SDR_NWE: U16.K8(~{WE}) ; port SDR_NWE
NetR376_1: R376.1 U12.F7(~{BYTE})
NetR397_2: R397.2 U16.J2(CKE)

Not connected (* = marked no-connect by the designer): U16 E3(NC)* E7(NC)* H3(NC)* H7(NC)* K2(NC)* K3(NC)*; U17 A6(NC)* E3(NC)*

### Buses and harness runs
bus A[0..23] = port A[0..23]
bus D[0..31] = port D[0..31]

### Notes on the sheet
- MEMORIES
- (Always ON)
- (*) Some SRAM I/Os are supplied by VDD_IO_MMC
  (make sure to control MFX0 & PG6)
  (see Power_Board page)
- A19-23 = 0 by default
- A20 = NC
- A23 = RFU
- PA7
- (near R397) PG15
- (near R397) PF11
- (near R397) PH6
- (near R142) PG10 (*) or PC8
- (near R397) PH7
- (near R397) PG8
- (near R109) PE1
- (near R109) PE0
- FMC_NBL1
- FMC_NBL0
- (near R91) PC7
- (near R376) Default config = A0-A18
- (near R376) (VDD_IO_MMC = 3.3V)
- (near U17) SRAM
- (near R91) PD5
- PC6
- PD4
- Default config = A0-A18
- (near U12) Nor Flash
- (near R134) SDRAM default config = 32 bits.
- (near R134) PI5
- PI4
- OCSPI2
- LIMITATIONS (SDRAM) :
- Default config = 32 bits.
- (near U16) SDRAM
- CAMERA
- LIMITATIONS (NOR) :
- OCSPI2, DFSDM DATIN3
- SD CARD : NE3 = PG10 (if SD CARD 1 is used) / PC8 (if SD CARD 2 is used)
- LIMITATIONS & BACK-UP (SRAM) :
- (*) Make sure to set VDD_IO_MMC = 3.3V
- Place close to SRAM
- Place close to Nor Flash
- Place close to SDRAM

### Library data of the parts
C43 C55 C134 C136-C141 C143 C145 C146 C149 C150 C152-C156 C158 = MCD-00006: as C56 on sheet Audio_Codec
C133 C142 C144 = MCD-04044: Capacitor, MLCC, 4.7uF, 10V, X5R, 20%, 0603, T=0.8mm; Manufacturer_Part_Number: C0603C475M8PAC7040; Manufacturer: KEMET CORPORATION; Part_Preference: Recommended; Component_Country_Of_Origin: Mexico; ShowFields: YES; ID: 6160
JP25 = MCD-00045: as JP22 on sheet MCU_Clock&Reset
R79 R84 R85 R91 R109 R134 R142 R143 R376 = MCD-00053: as R402 on sheet Audio_Codec
R86 R92 R107 R336 R346 = MCD-00164: Resistor,220K,0402,1%,1/16W; Manufacturer_Part_Number: RC0402FR-07220KL; Manufacturer: YAGEO; Part_Preference: Recommended; Provided_By: SUBCO; ECCN_US: EAR99; ECCN_EU: NEC; Component_Country_Of_Origin: China; ID: 2704; ShowFields: YES
R397 = MCD-00052: as R135-R137 on sheet Audio_Codec
U12 = MCD-01345: NOR FLASH 128Mbit 75ns - 64-ball LBGA (replacing PC28F128M29EWLA); Part_Type: IC; Manufacturer: MICRON; BMS_Part_Number: 9171980; Part_Preference: Recommended; Provided_By: SUBCO; ECCN_US: 3A991; ECCN_EU: NEC; Component_Country_Of_Origin: Singapore°; ID: 3445; ShowFields: YES
U16 = MCD-00562: SDRAM 256MBit 166MHZ 90BGA; Part_Type: IC; Manufacturer: ISSI; Part_Preference: Recommended; Provided_By: SUBCO; ECCN_US: EAR99; ECCN_EU: NEC; Component_Country_Of_Origin: China, Taiwan°°; ID: 3182; ShowFields: YES
U17 = MCD-00560: SRAM 16Mb 10ns 1Mx16 Async SRAM 3.3v; Manufacturer: ISSI; Part_Type: IC; BMS_Part_Number: 9171285; Part_Preference: Recommended; Provided_By: SUBCO; Component_Country_Of_Origin: Taiwan°; ID: 3185; ShowFields: YES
